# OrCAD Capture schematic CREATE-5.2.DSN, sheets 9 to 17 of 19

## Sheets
9 P18: changes since K4R3.3: title: Change Log
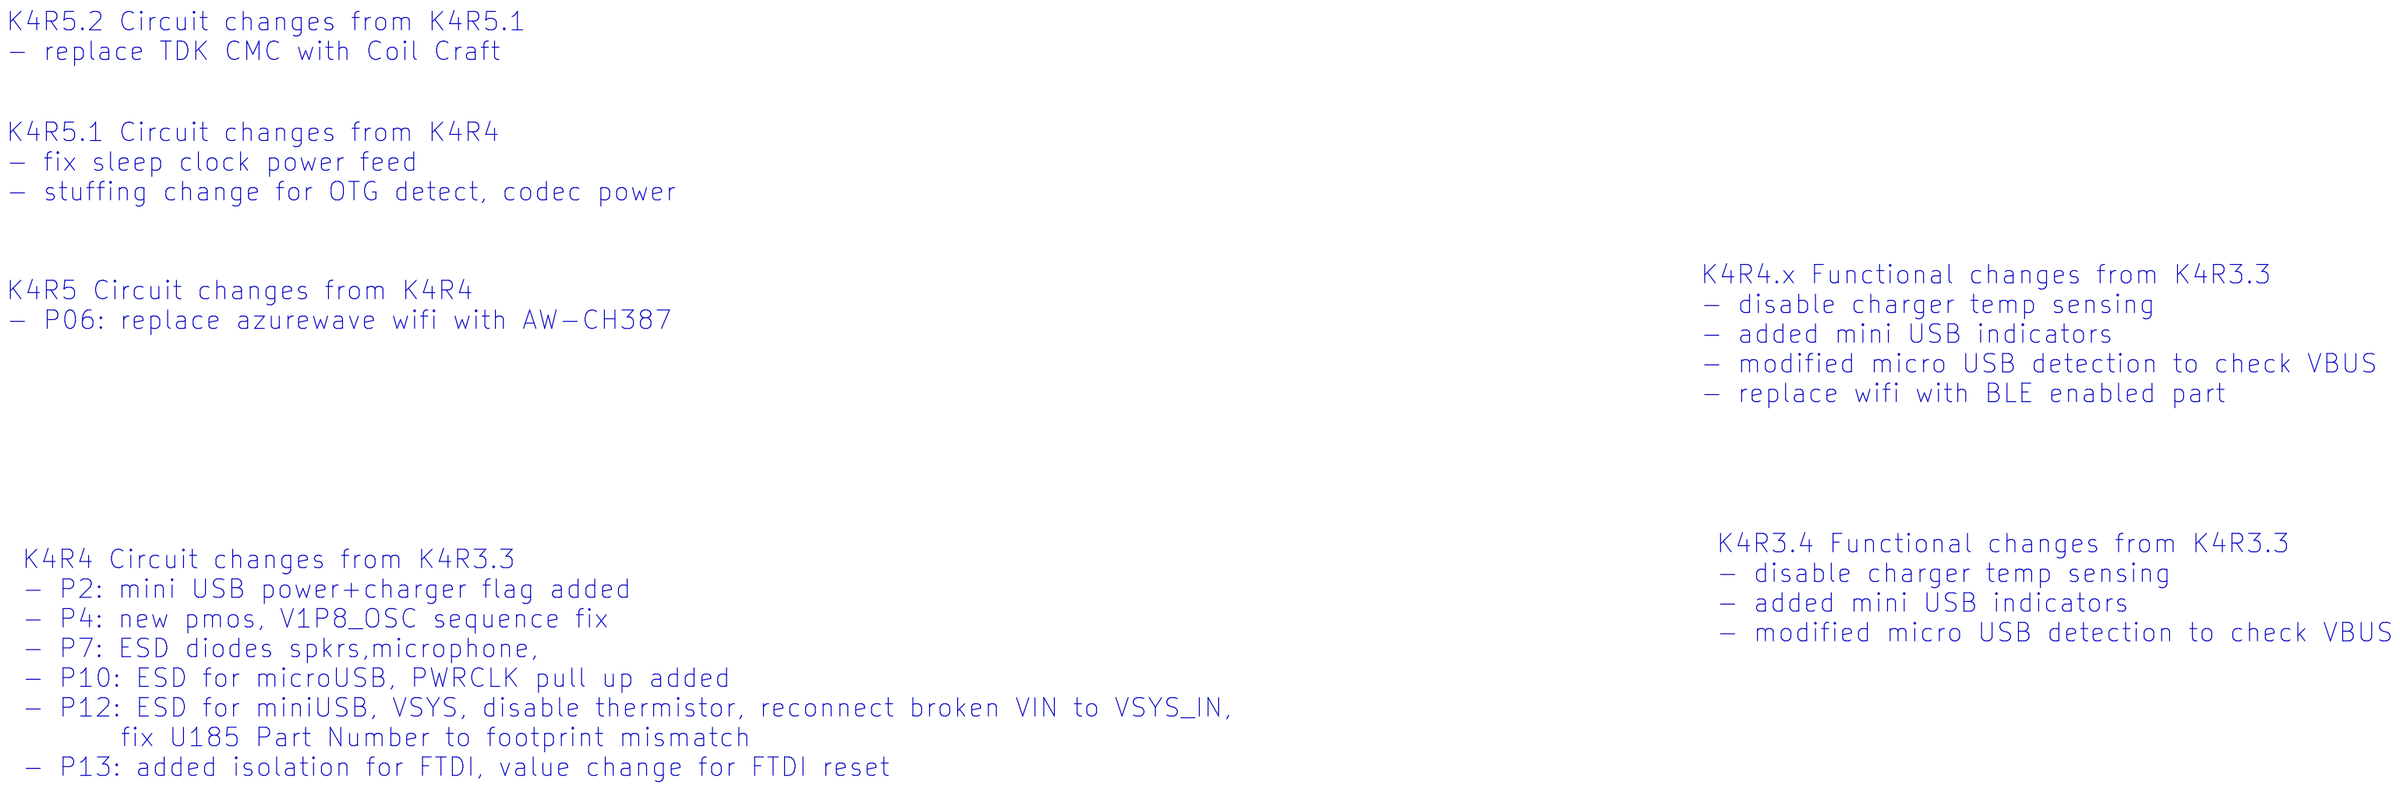
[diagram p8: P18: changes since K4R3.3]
10 P11: System Power Rails: size Custom; title: System Power
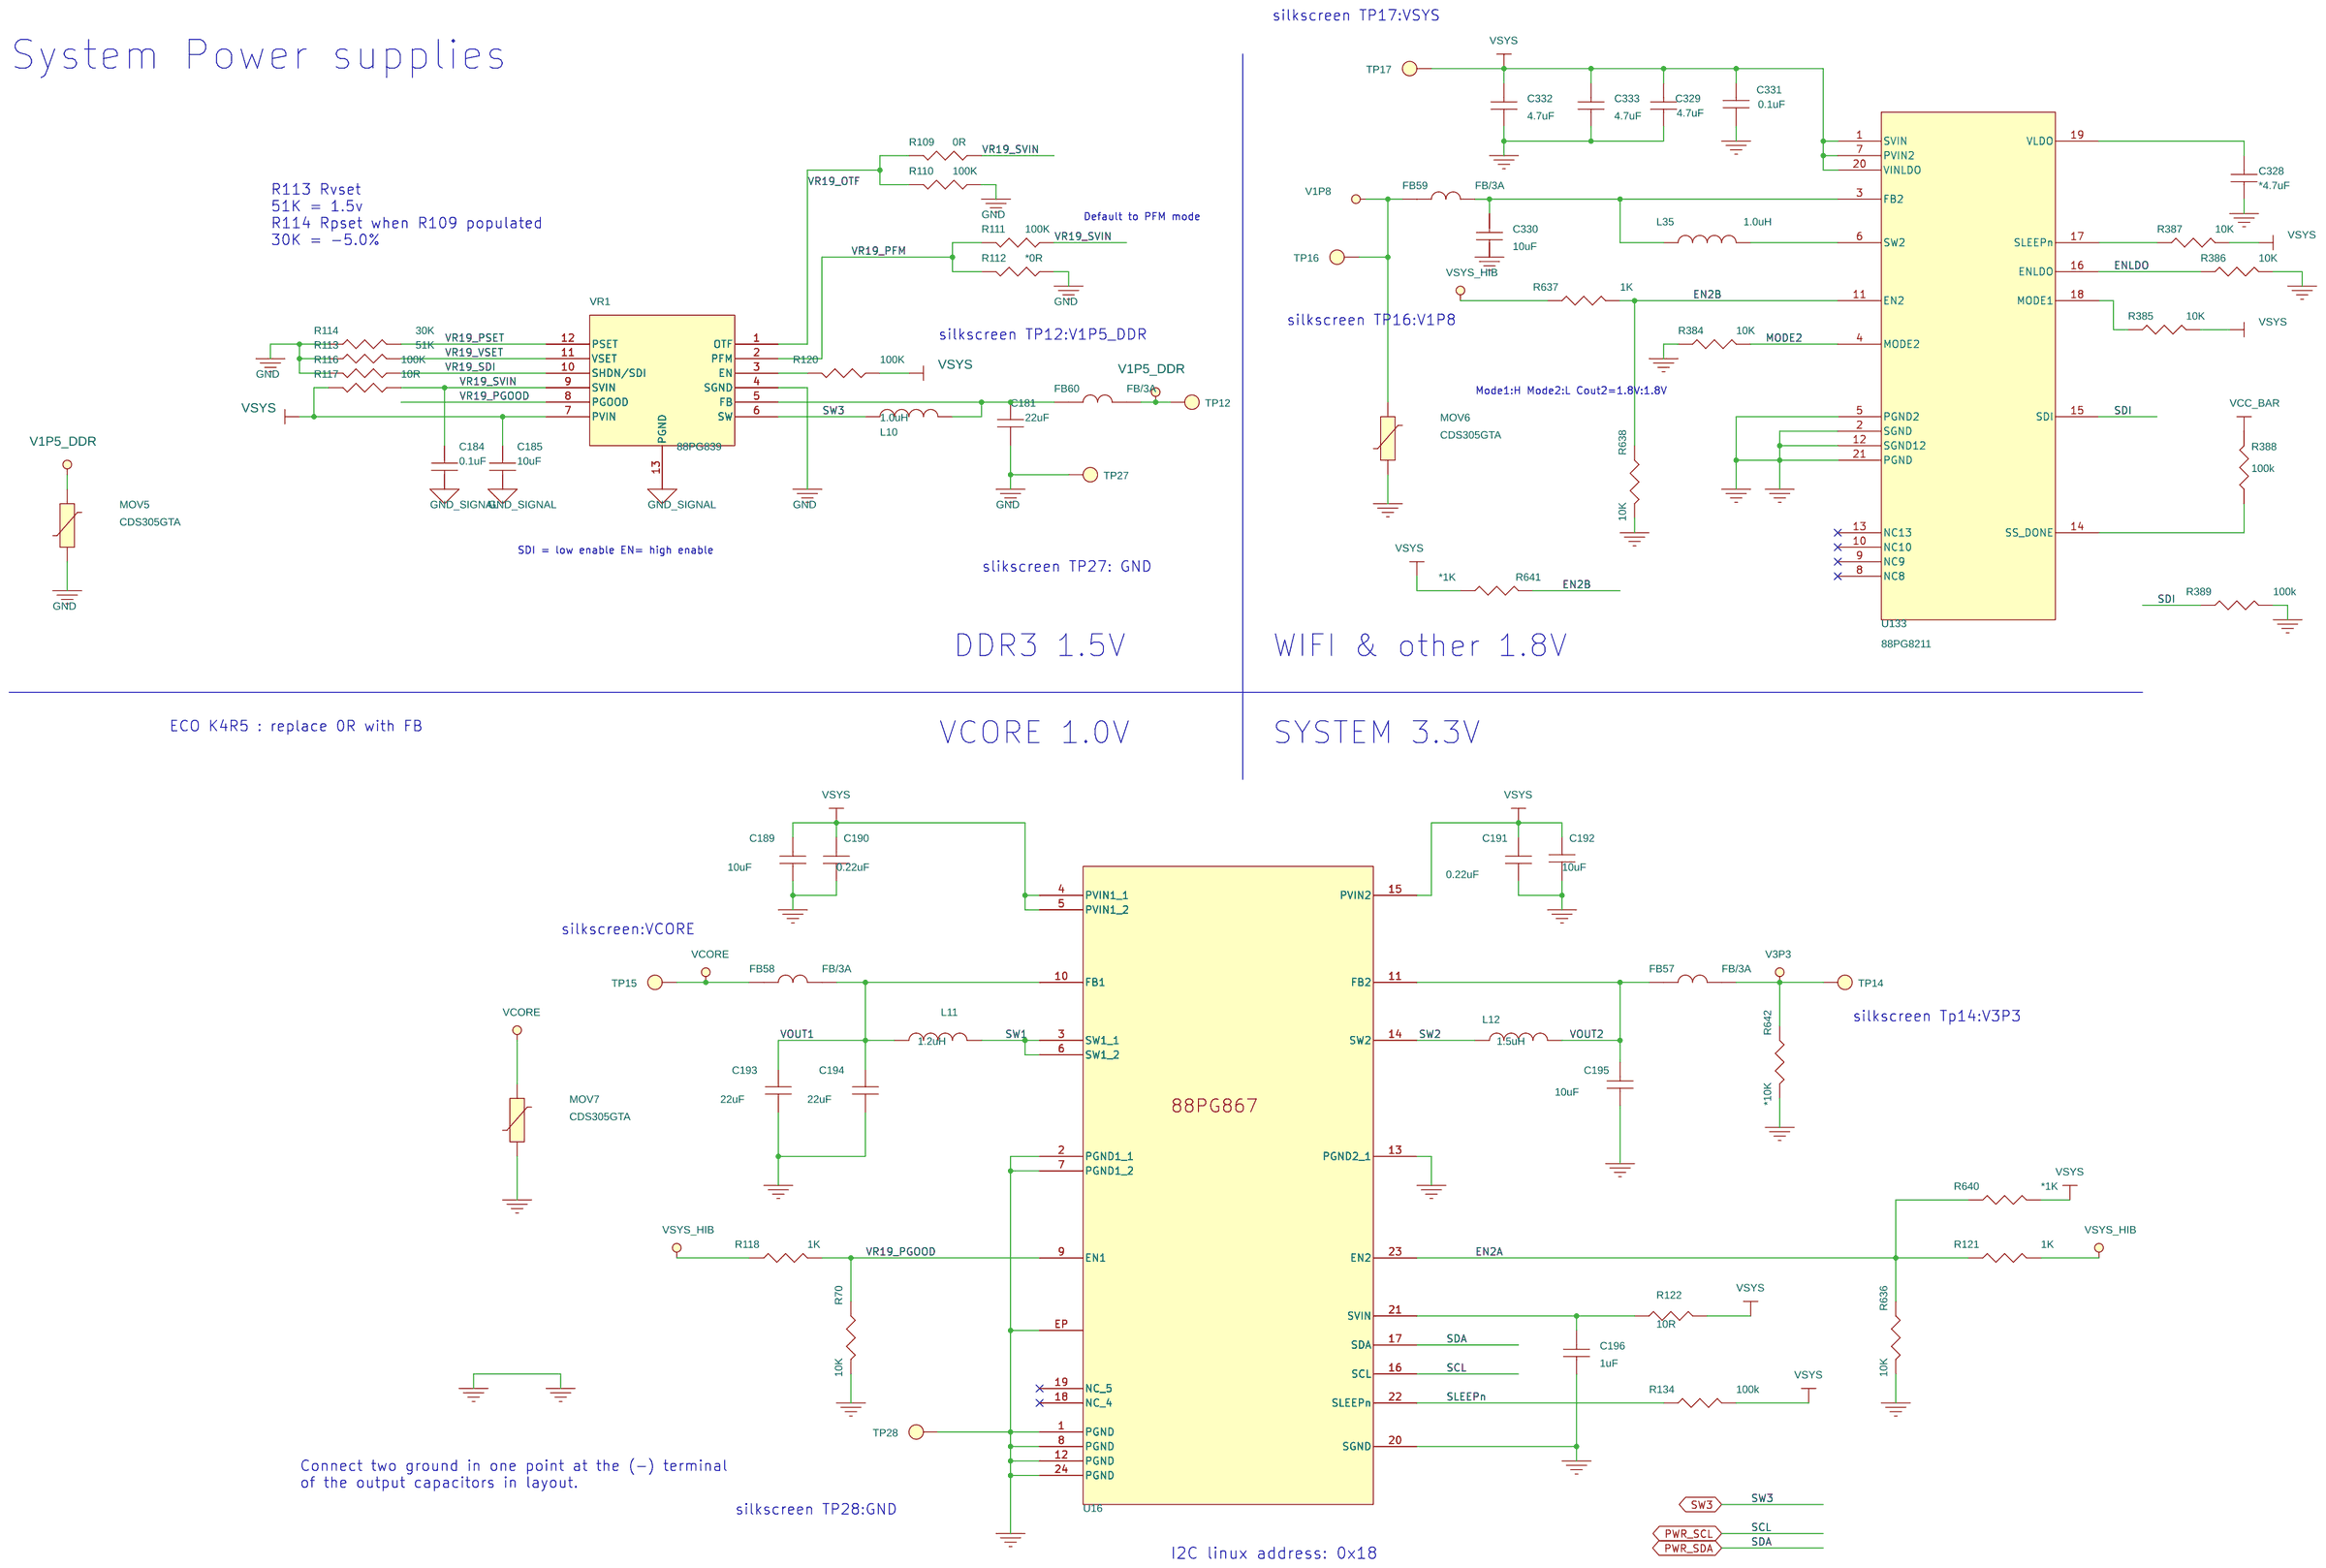
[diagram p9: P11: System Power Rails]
11 P09: Power architecture: title: Power Distribution
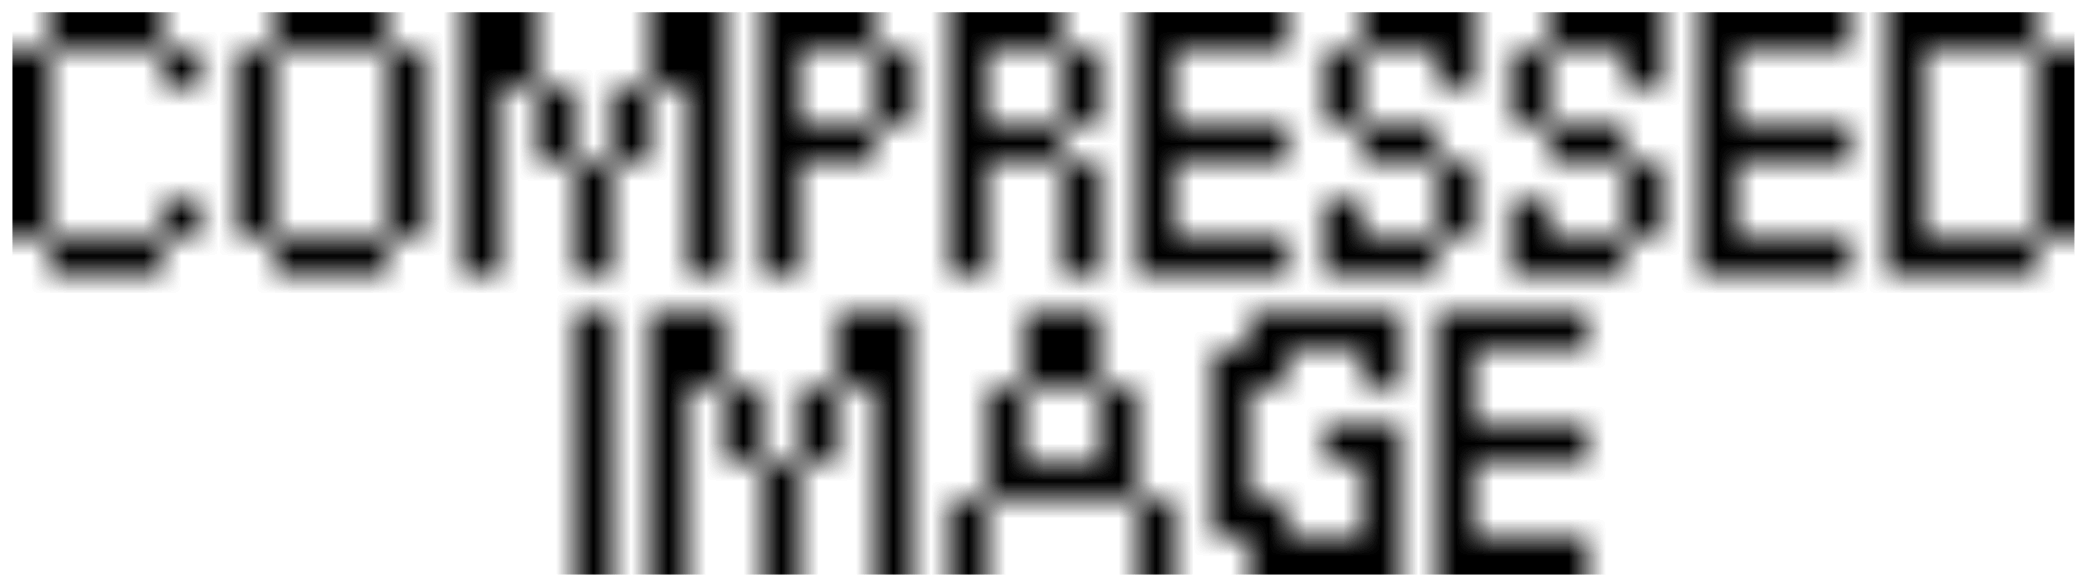
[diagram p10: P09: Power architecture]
12 P01: Create Block Diagram: title: Main Board; rev: 5.1
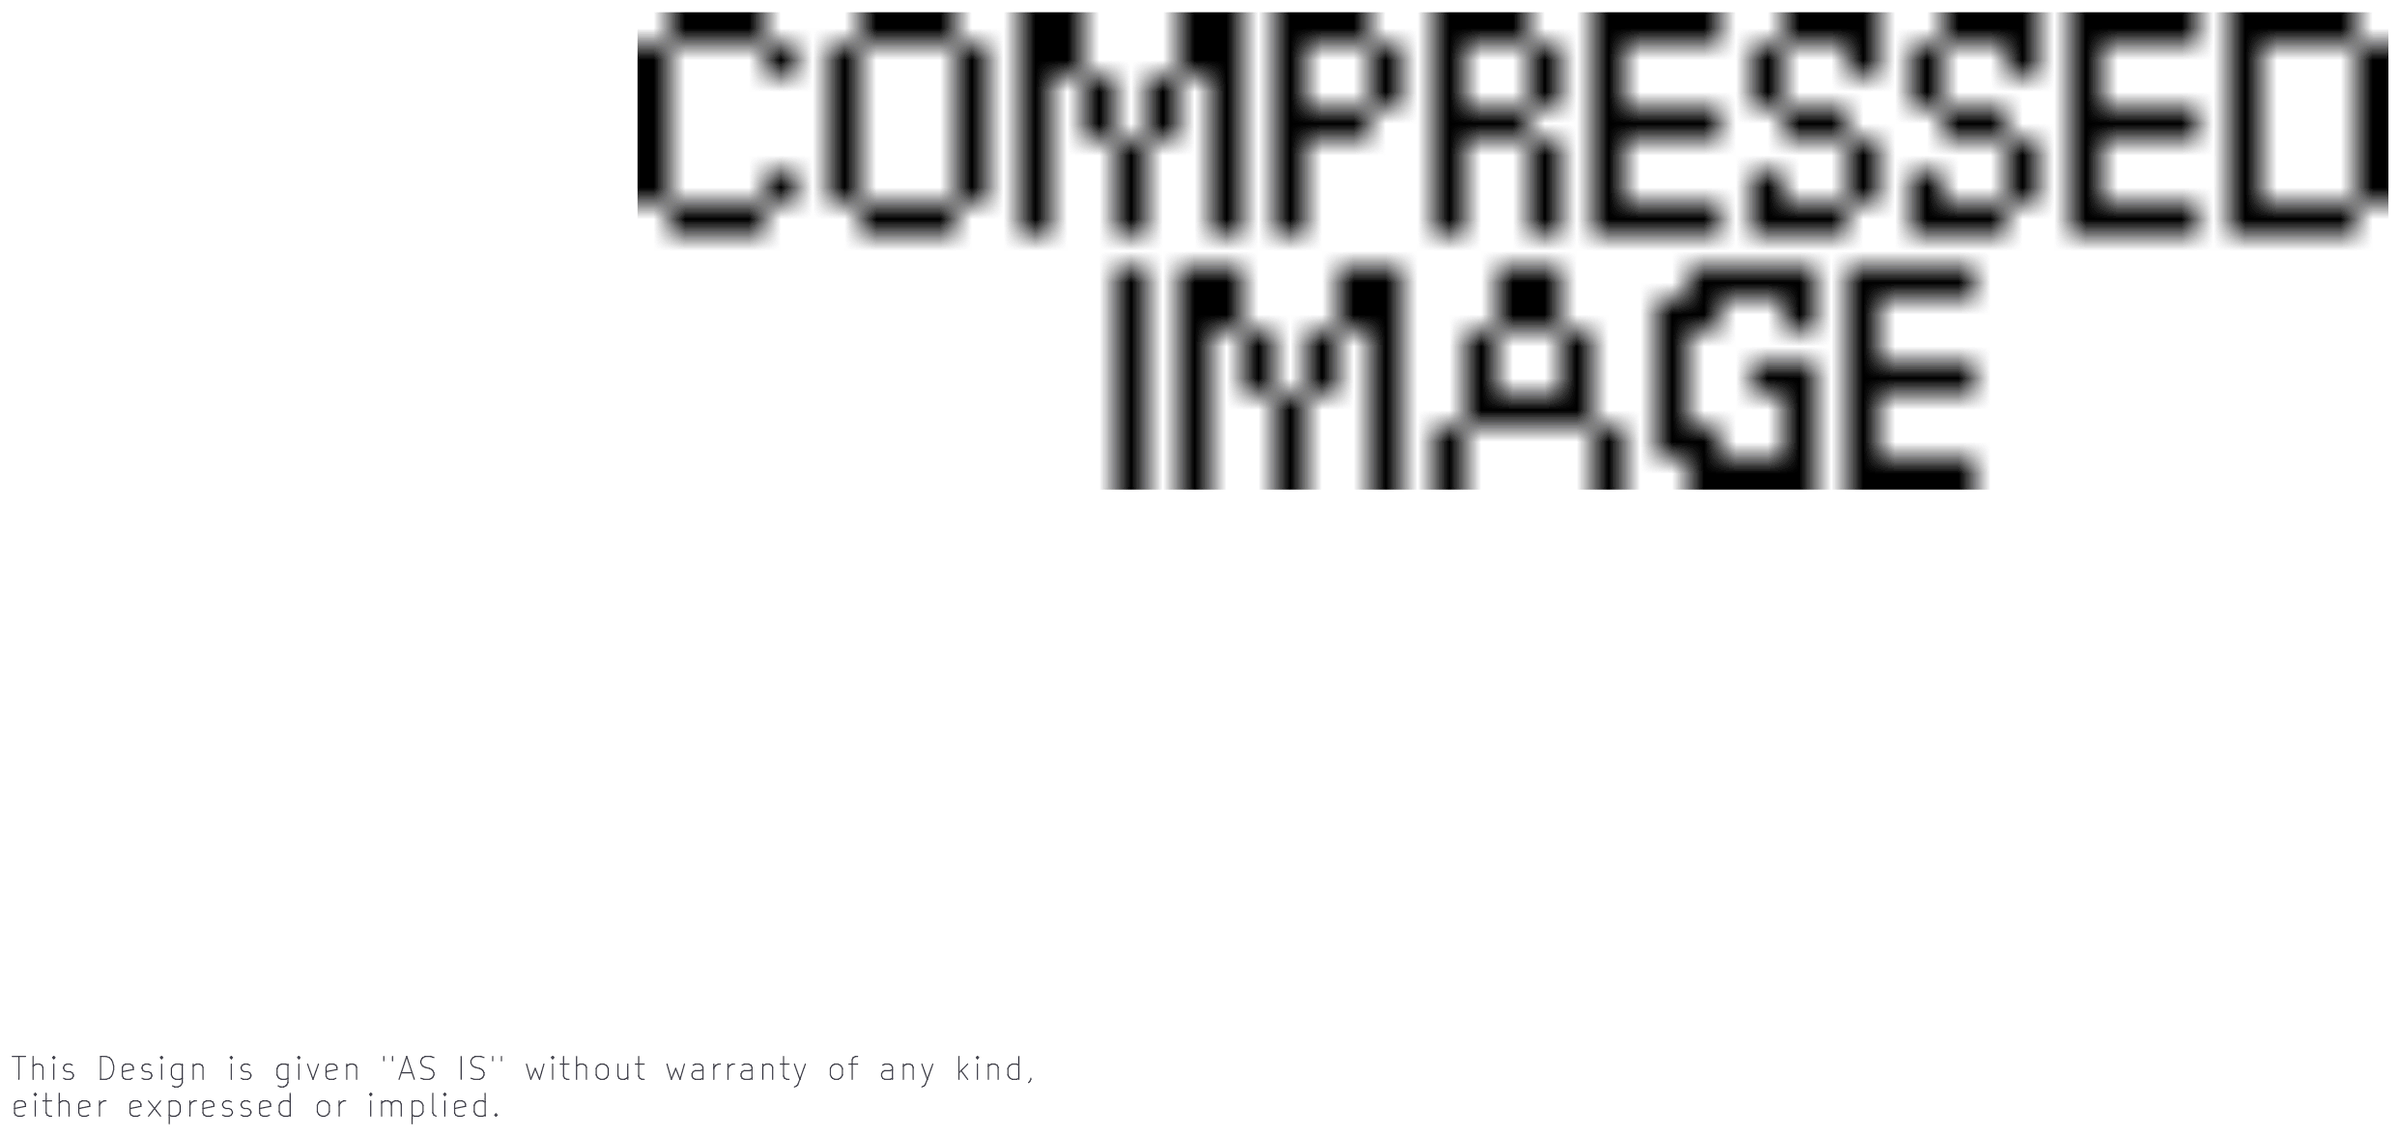
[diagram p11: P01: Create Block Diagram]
13 P10: Power Input and switch: size Custom; title: Power Input & switch
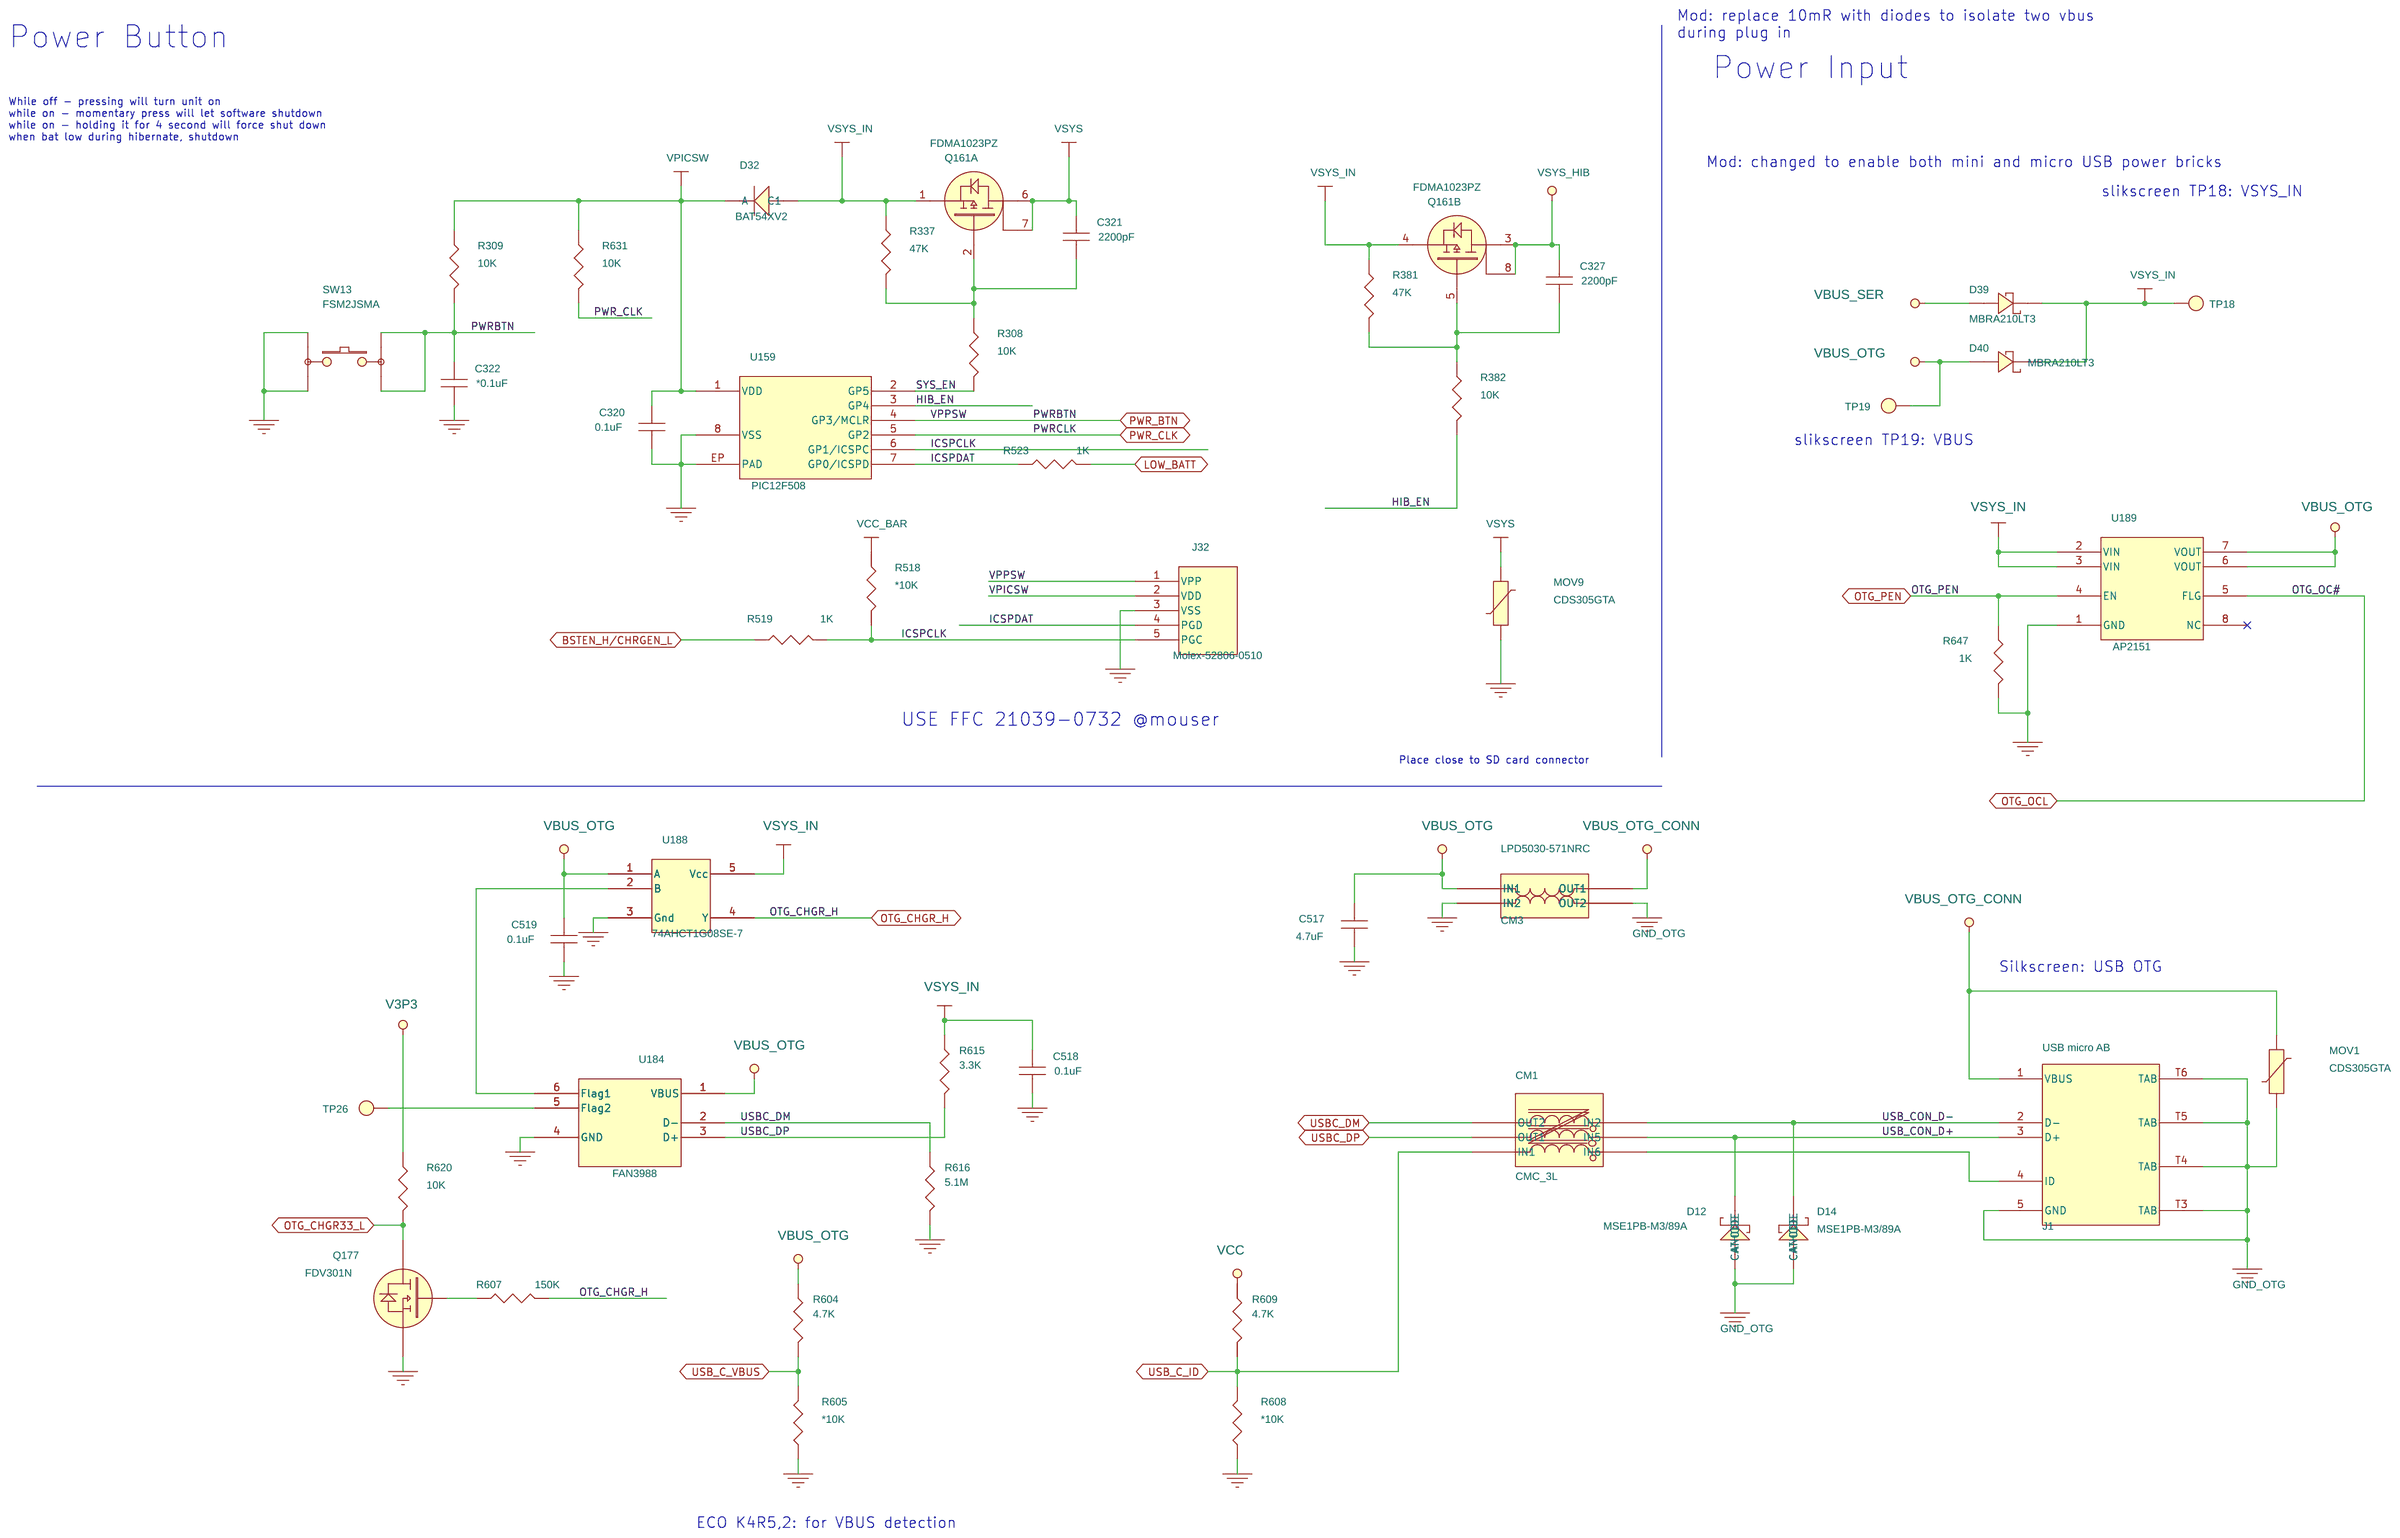
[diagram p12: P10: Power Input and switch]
14 P03: ASPEN-AUDIO/SDIO/MISC: size Custom; title: ASPEN-SPI/SDIO/etc
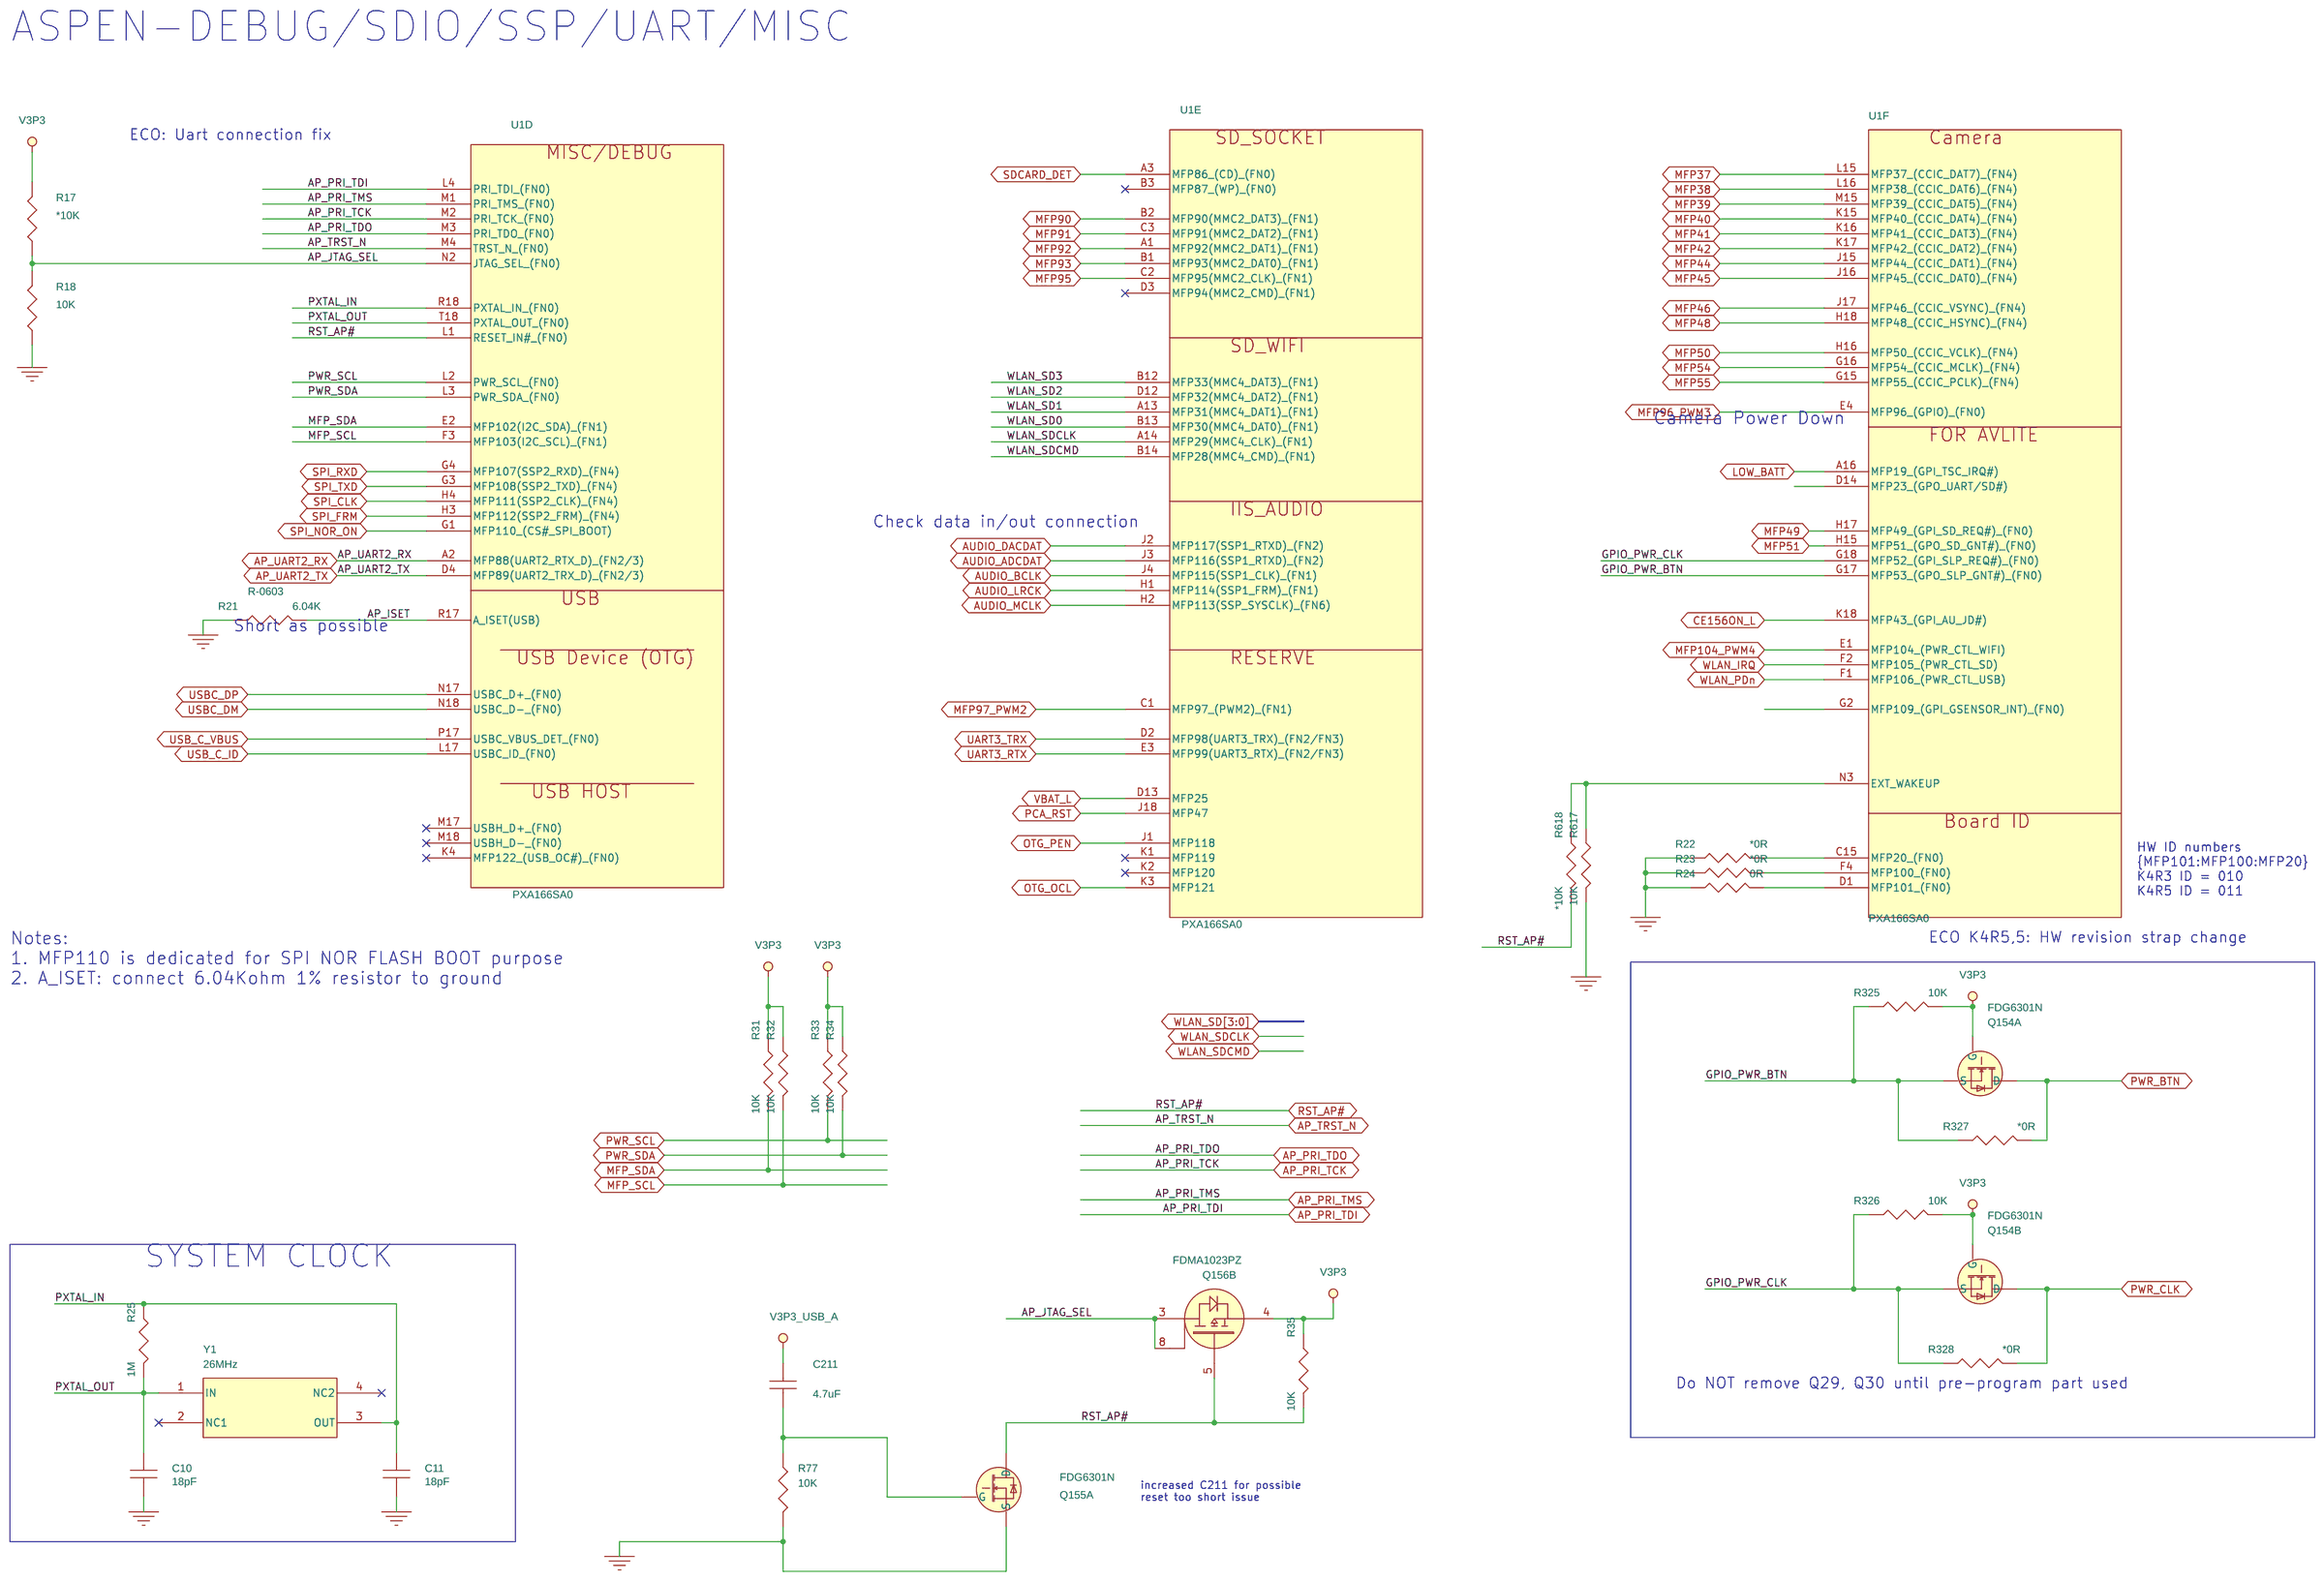
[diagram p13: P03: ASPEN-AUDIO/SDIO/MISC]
15 P19: changes K4R2 to K4R3.3: title: Change Log
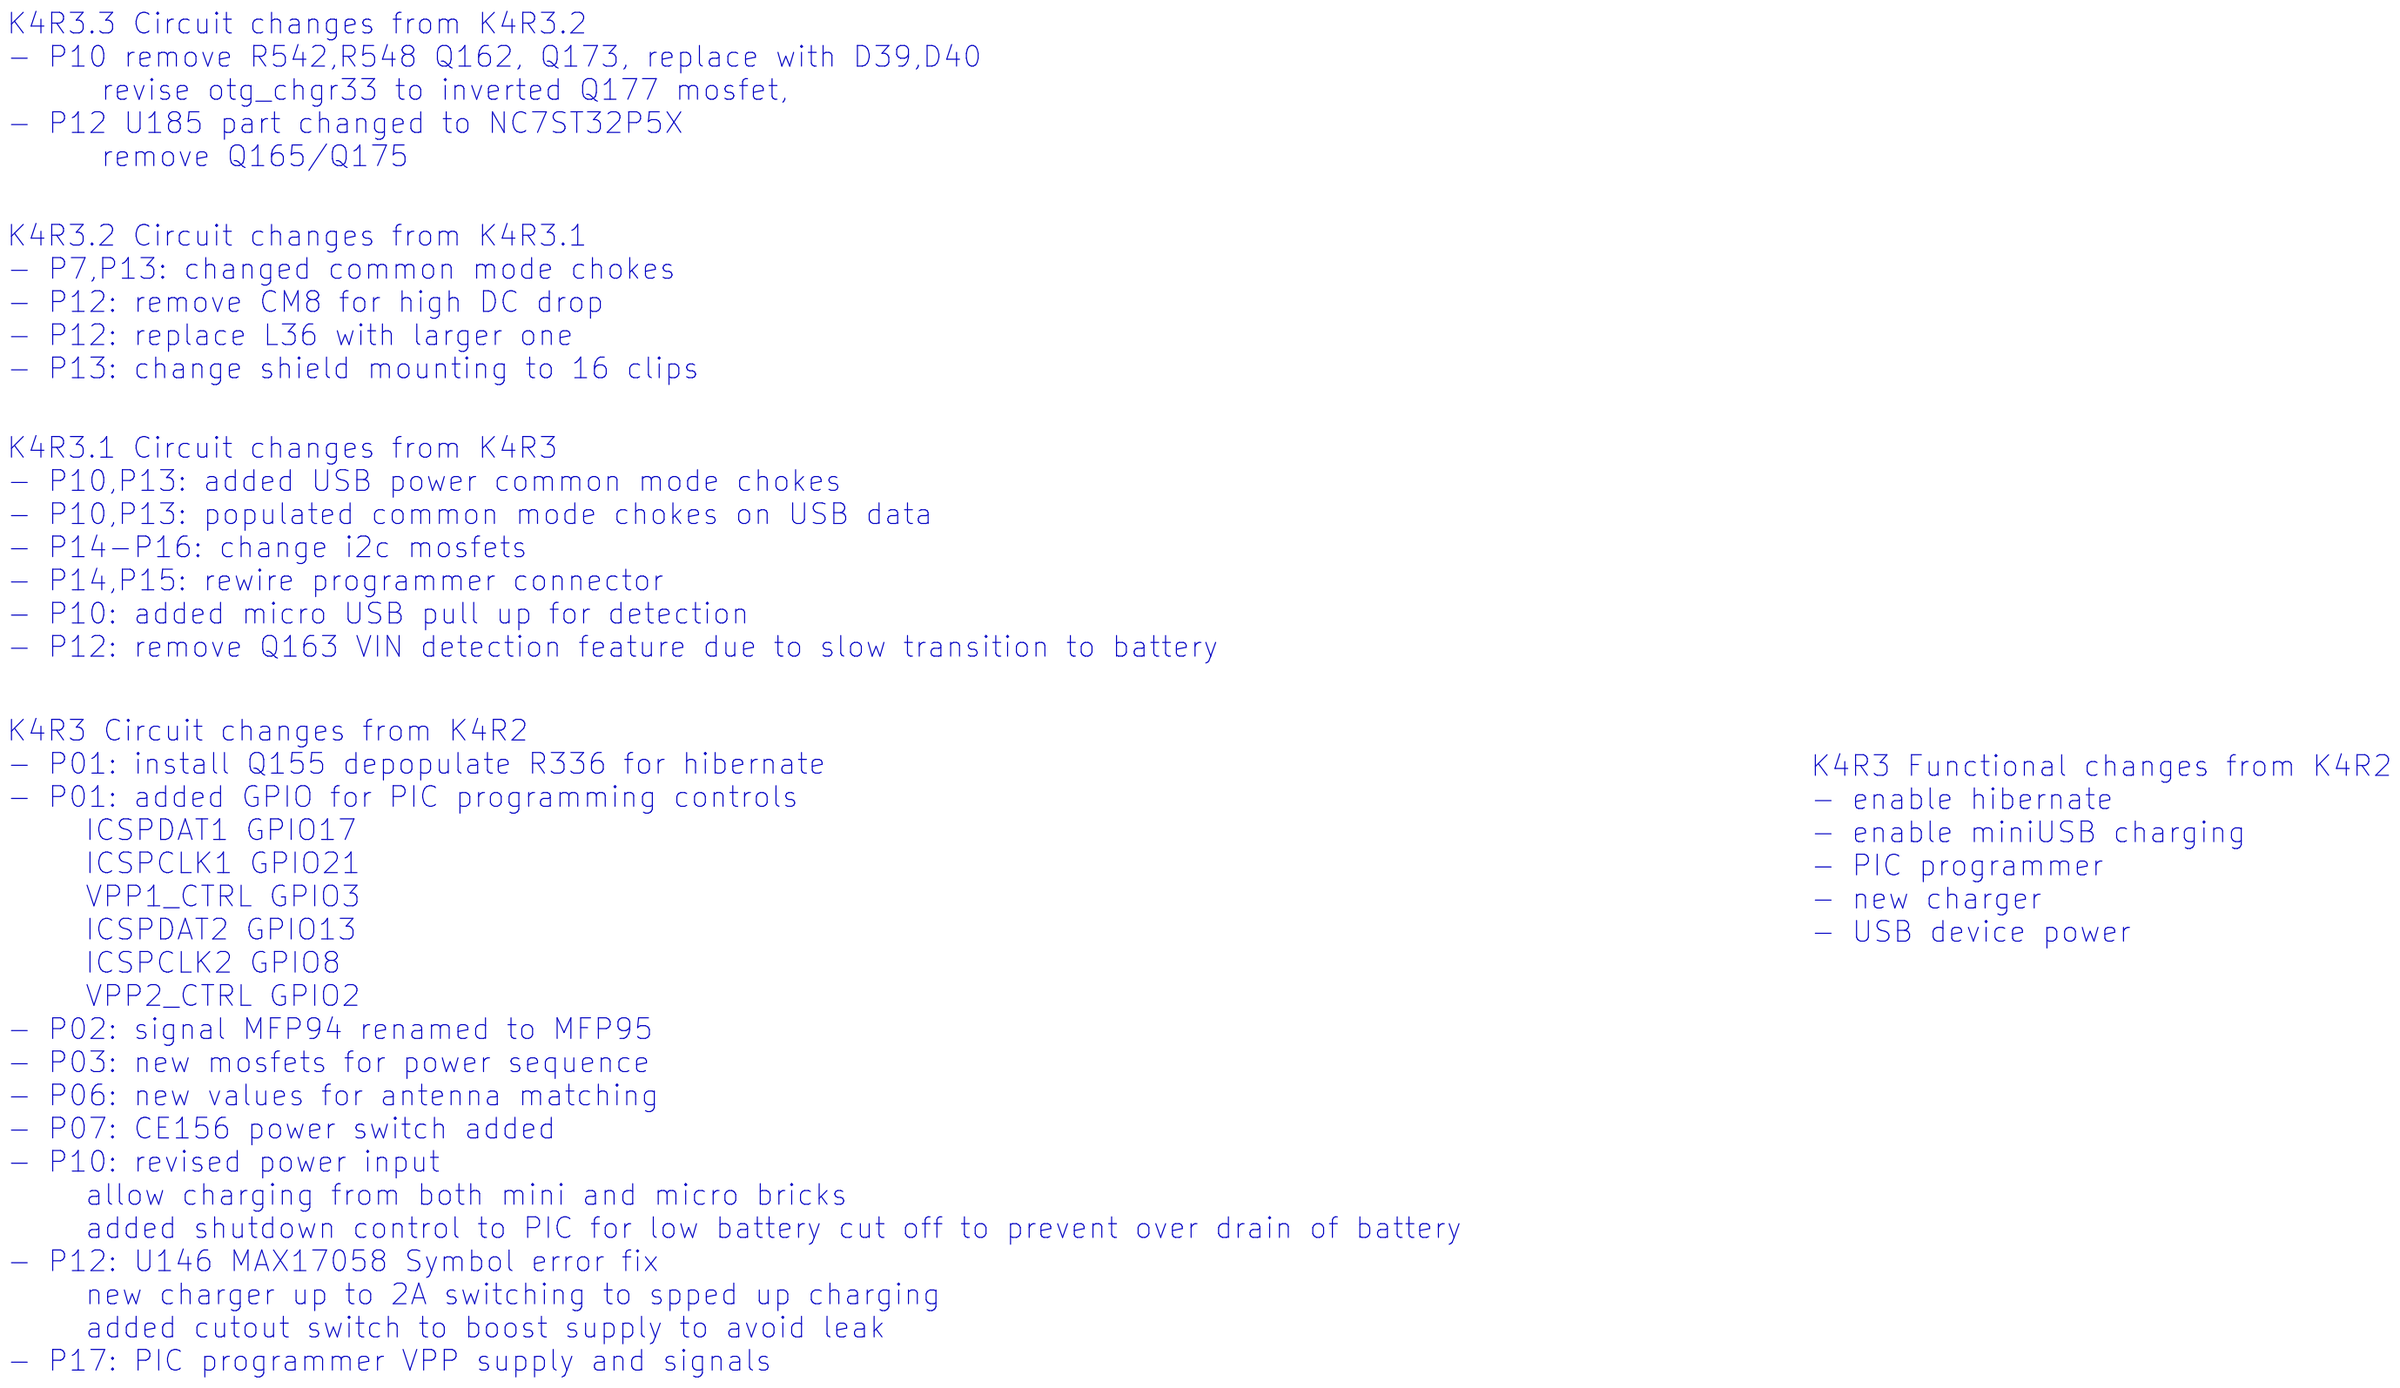
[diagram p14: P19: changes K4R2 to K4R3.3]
16 P12: batt, GG, Bst and chgr: size Custom; title: Power Path
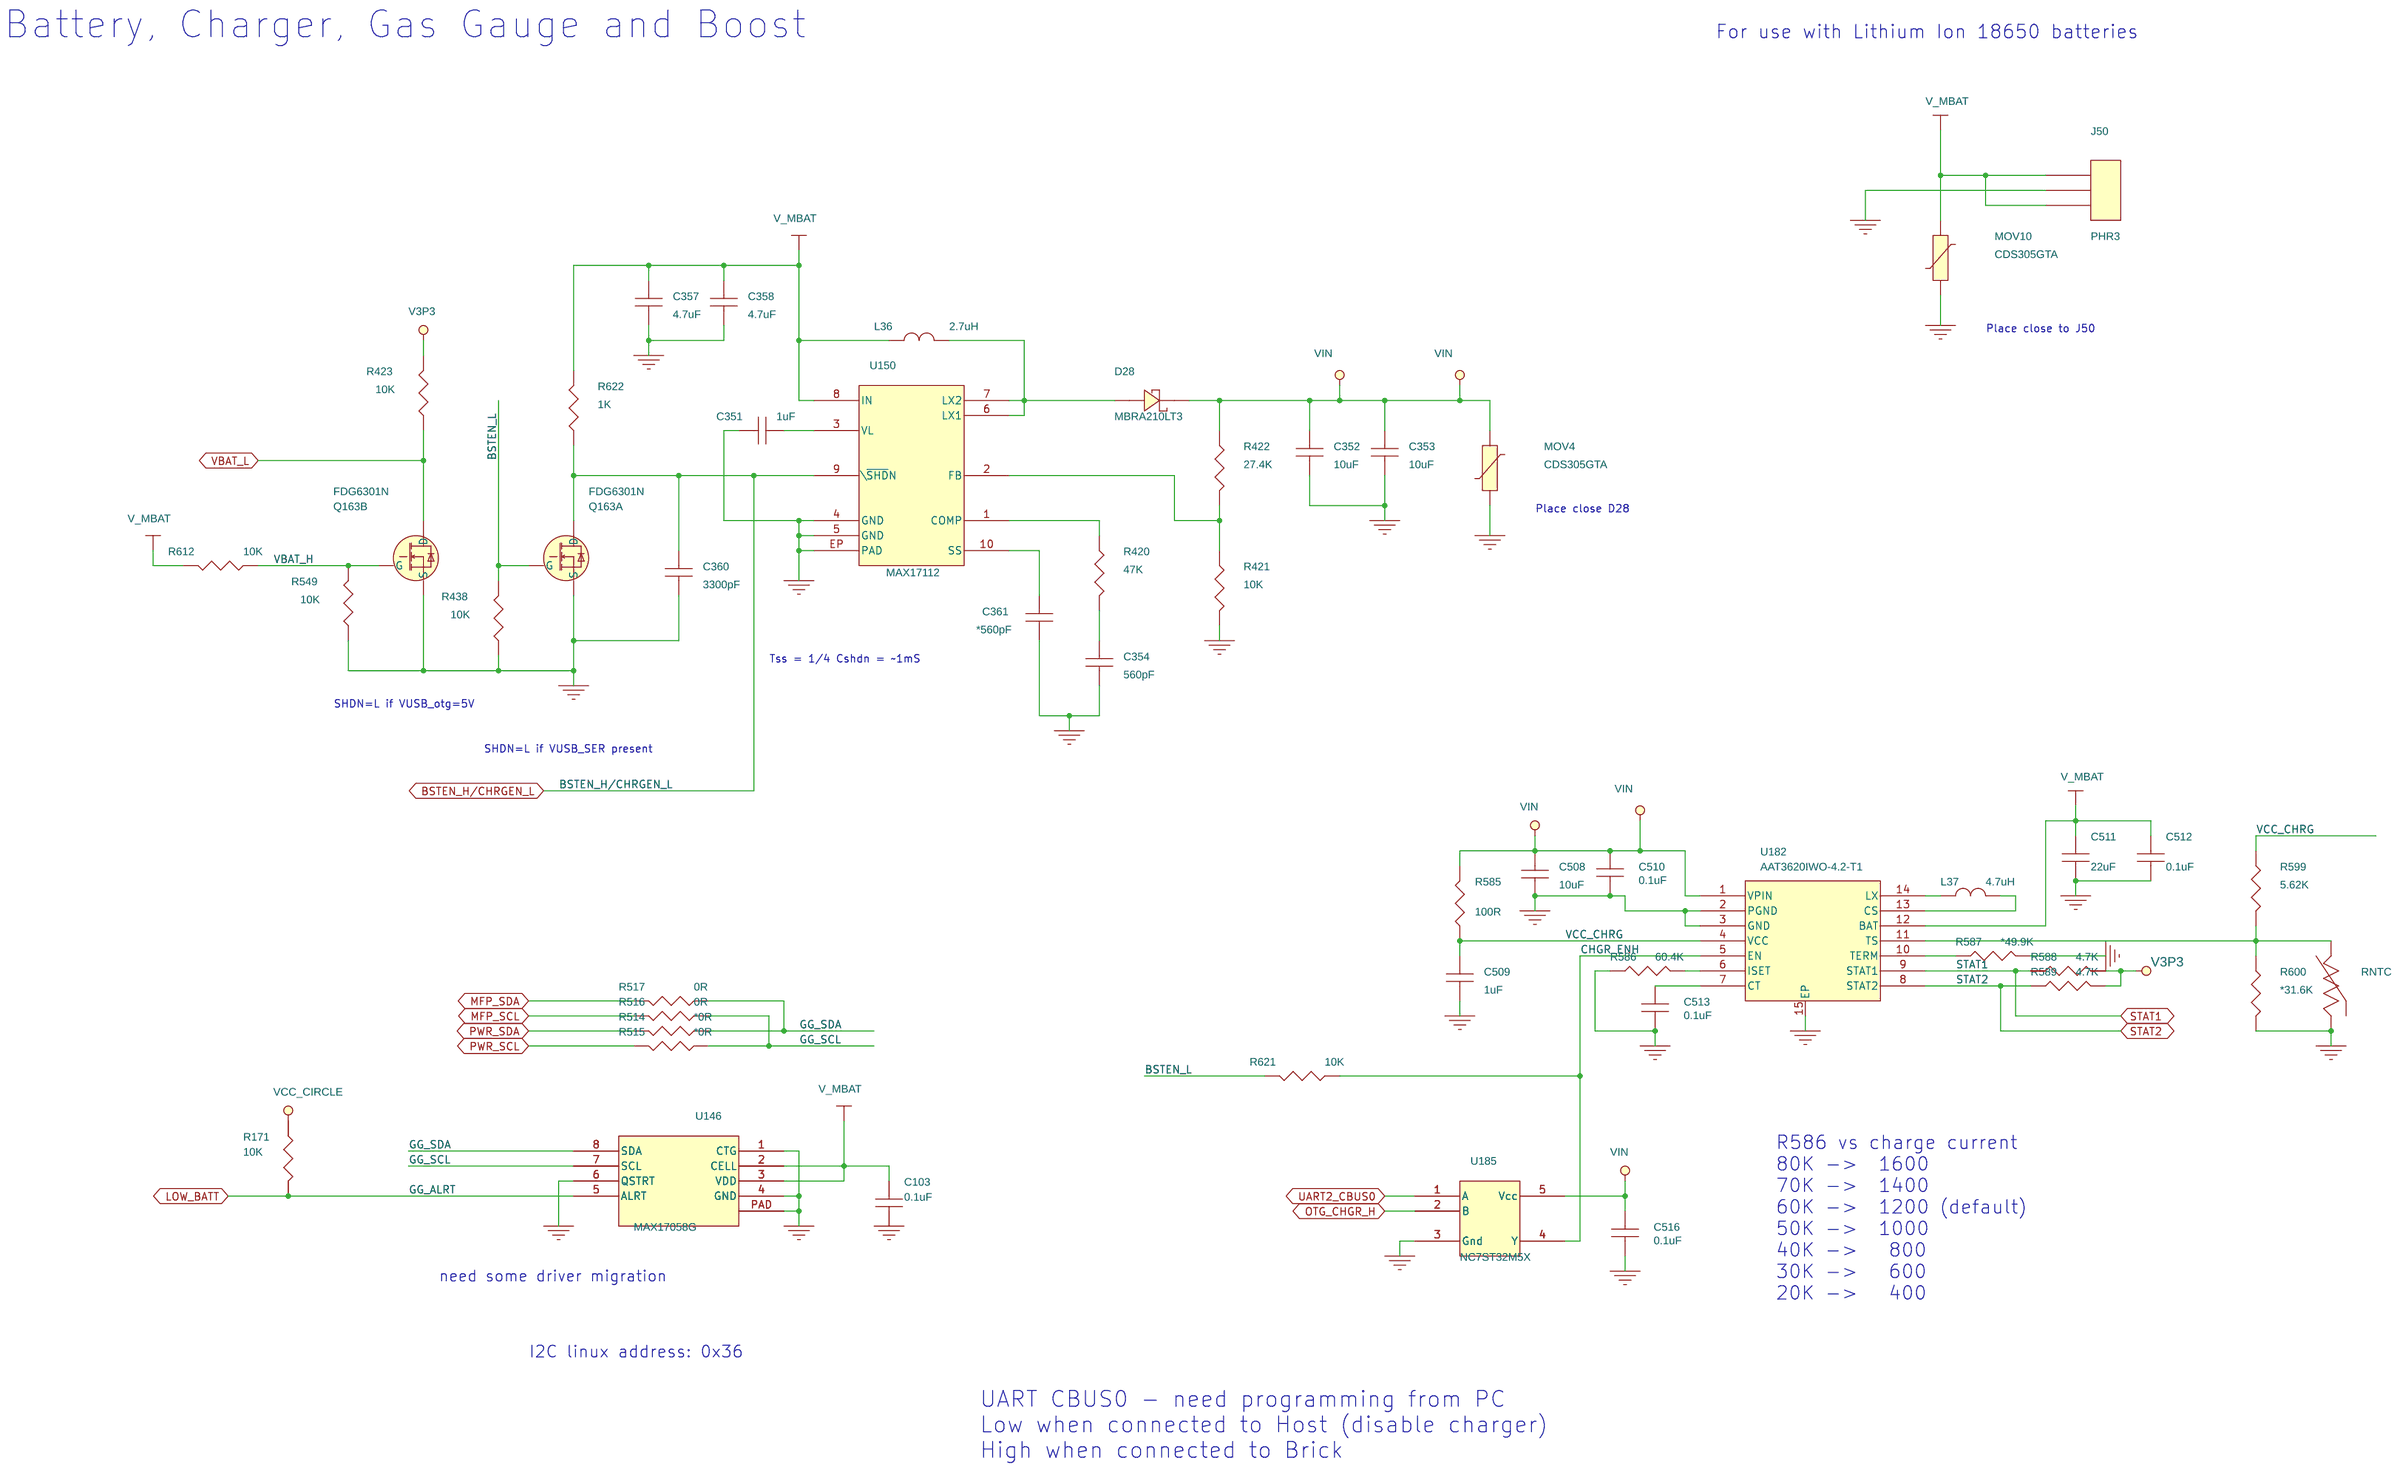
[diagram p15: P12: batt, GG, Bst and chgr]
17 P14: Front access 8 pin conn 1: size Custom; title: Front Conn 1
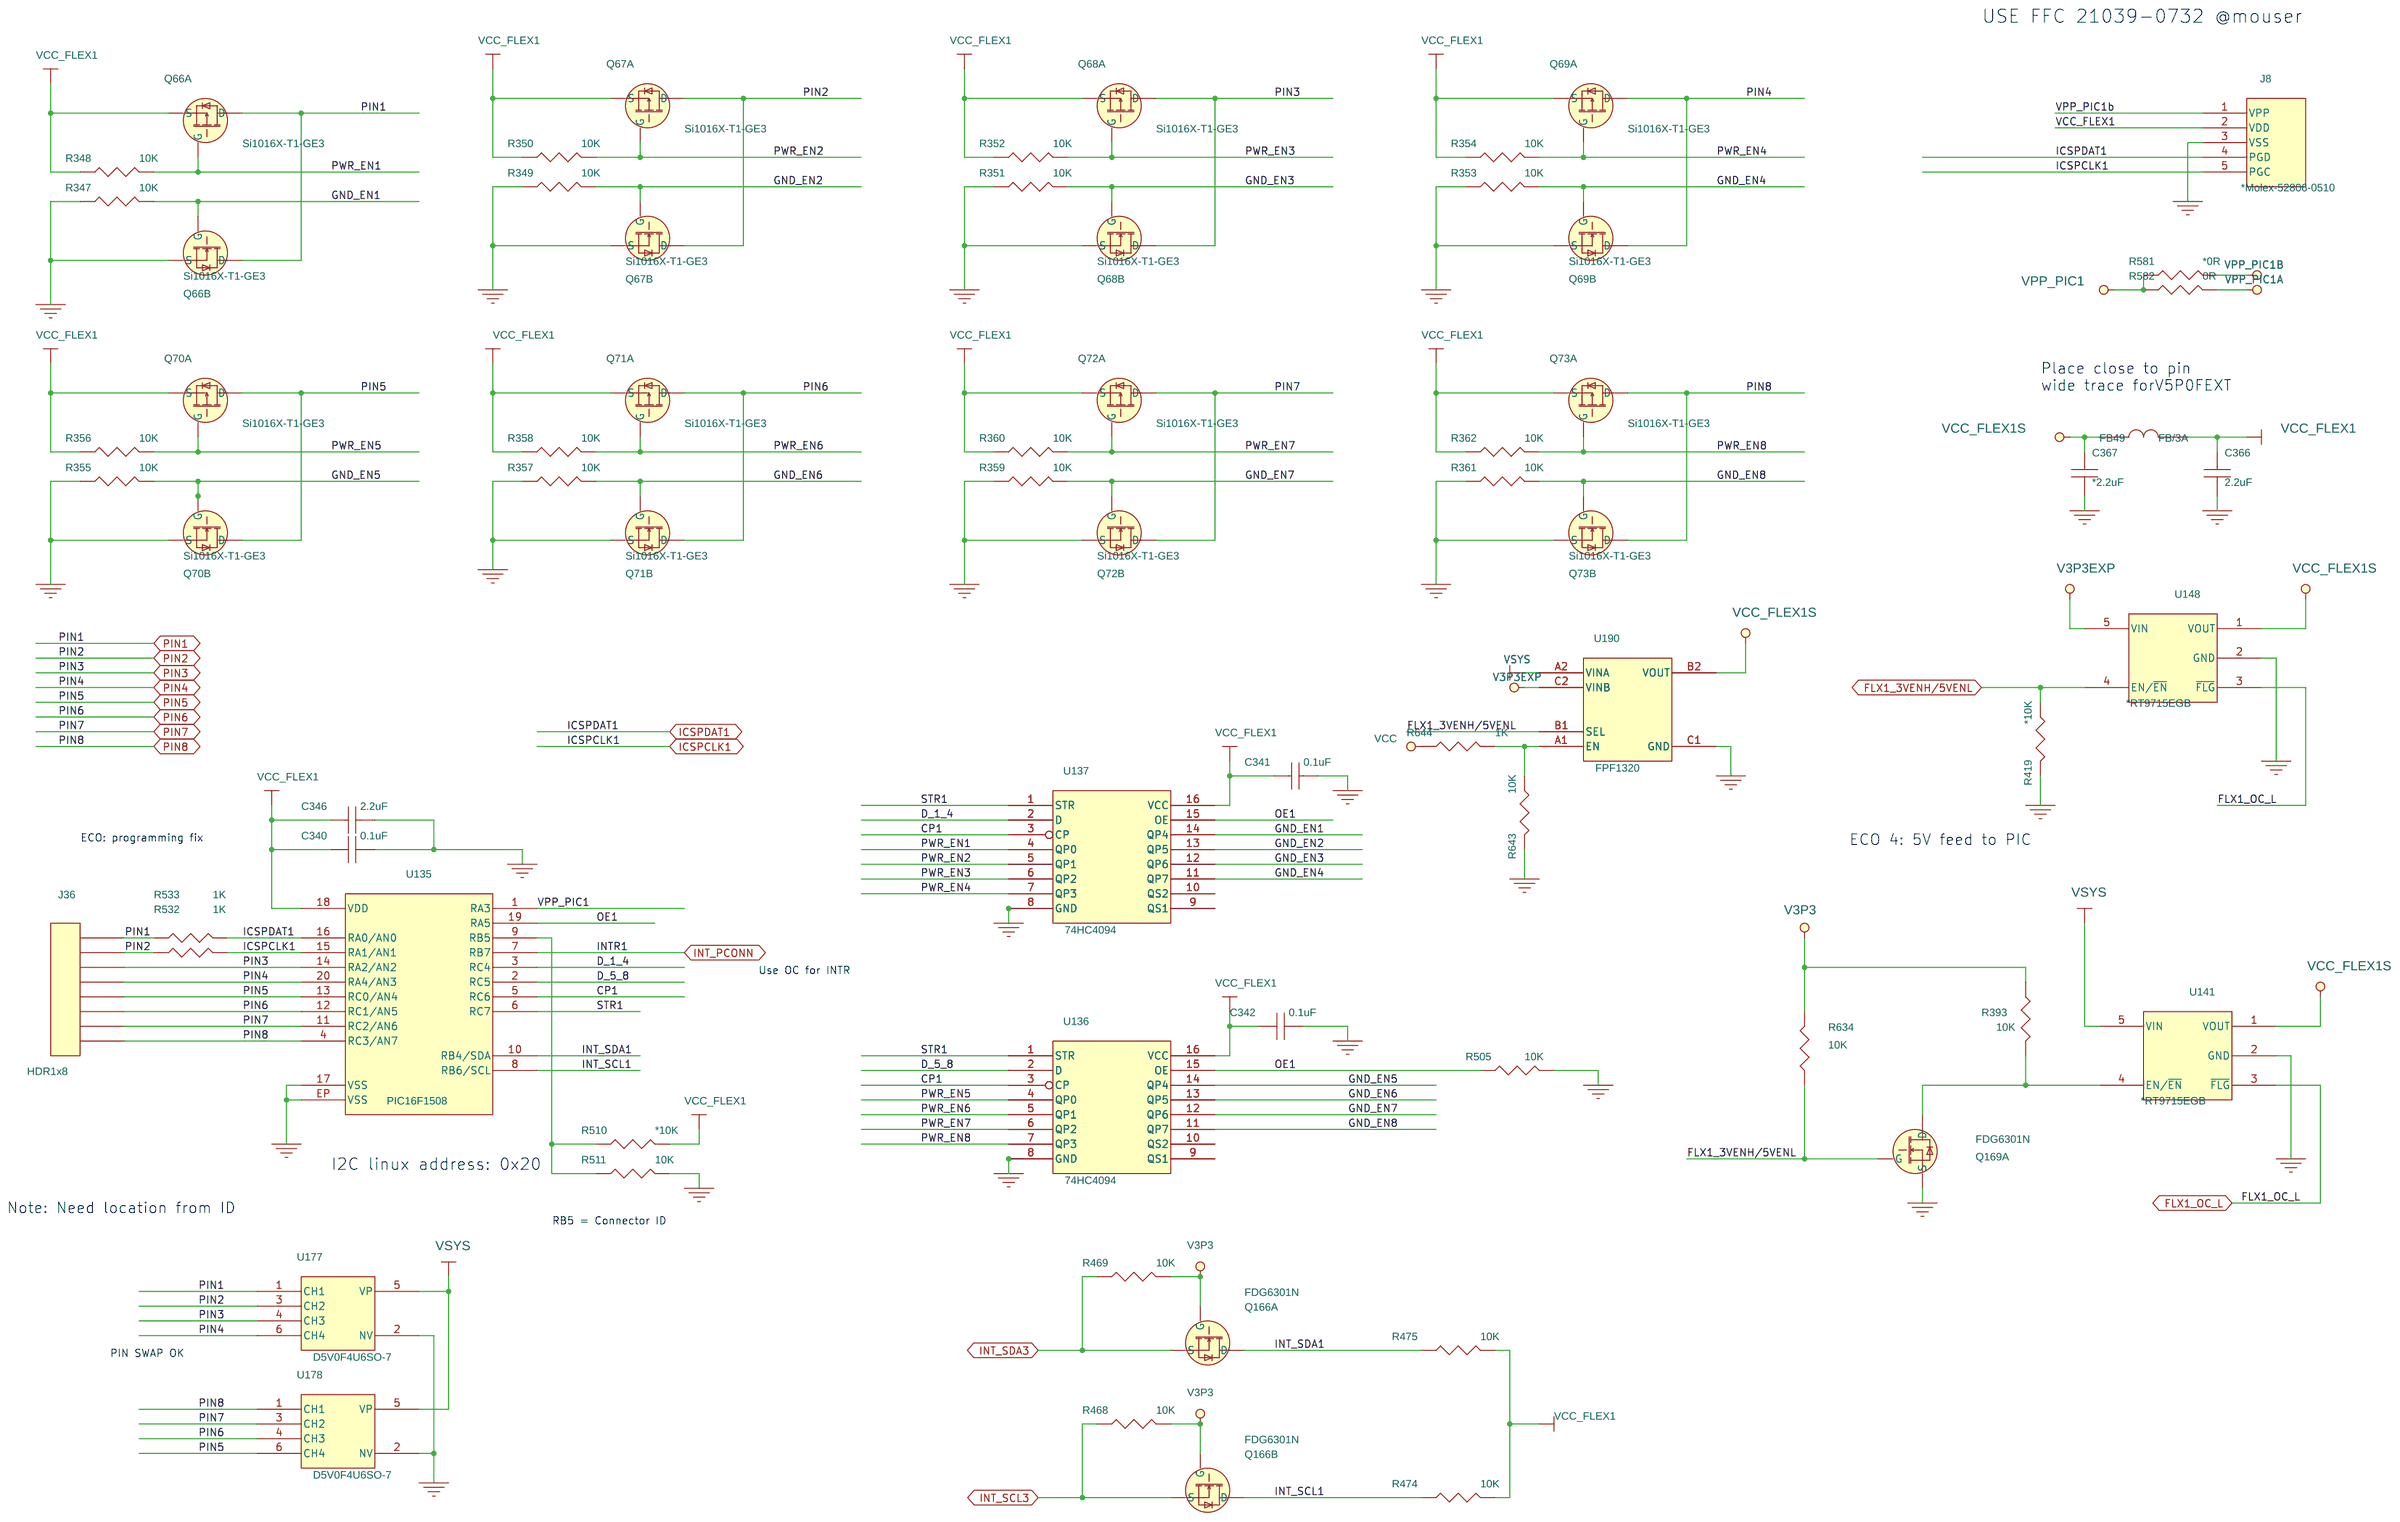
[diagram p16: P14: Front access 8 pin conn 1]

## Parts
sheet P02: ASPEN-MEM/USB/LCD
Q155  FDG6301N  [SC70-6]  (sections A,B)
sheet P03: ASPEN-AUDIO/SDIO/MISC
C10  18pF  [C-0402]
C11  18pF  [C-0402]
C211  4.7uF  [C-0402]
Q154  FDG6301N  [SC70-6]  (sections A,B)
Q156  FDMA1023PZ  [WDFN6]  (sections A,B)
R17  *10K  [R-0402]
R18  10K  [R-0402]
R21  6.04K  [R-0603]
R22  *0R  [R-0402]
R23  *0R  [R-0402]
R24  0R  [R-0402]
R25  1M  [R-0402]
R31  10K  [R-0402]
R32  10K  [R-0402]
R33  10K  [R-0402]
R34  10K  [R-0402]
R35  10K  [R-0402]
R77  10K  [R-0402]
R325  10K  [R-0402]
R326  10K  [R-0402]
R327  *0R  [R-0402]
R328  *0R  [R-0402]
R617  10K  [R-0402]
R618  *10K  [R-0402]
U1  PXA166SA0  [fbga-18x18-320]  (sections A,B,C,D,E,F)
Y1  26MHz  [o-3_2X2_5-4g]
sheet P10: Power Input and switch
C320  0.1uF  [C-0402]
C321  2200pF  [C-0402]
C322  *0.1uF  [C-0402]
C327  2200pF  [C-0402]
C517  4.7uF  [C-0603]
C518  0.1uF  [C-0402]
C519  0.1uF  [C-0402]
CM1  CMC_3L  [TDK2520-3L]
CM3  LPD5030-571NRC  [LPD5030]
D12  MSE1PB-M3/89A  [MicroSMP]
D14  MSE1PB-M3/89A  [MicroSMP]
D32  BAT54XV2  [SOD-523F]
D39  MBRA210LT3  [SMA]
D40  MBRA210LT3  [SMA]
J1  USB micro AB  [USB-MICRO-AB-HIROSE]
J32  Molex-52806-0510  [Molex_52806_0510]
MOV1  CDS305GTA  [D0603]
MOV9  CDS305GTA  [D0603]
Q161  FDMA1023PZ  [WDFN6]  (sections A,B)
Q177  FDV301N  [SOT-23a]
R308  10K  [R-0402]
R309  10K  [R-0402]
R337  47K  [R-0402]
R381  47K  [R-0402]
R382  10K  [R-0402]
R518  *10K  [R-0402]
R519  1K  [R-0402]
R523  1K  [R-0402]
R604  4.7K  [R-0402]
R605  *10K  [R-0402]
R607  150K  [R-0402]
R608  *10K  [R-0402]
R609  4.7K  [R-0402]
R615  3.3K  [R-0402]
R616  5.1M  [R-0402]
R620  10K  [R-0402]
R631  10K  [R-0402]
R647  1K  [R-0402]
SW13  FSM2JSMA  [FSM2JSMATR]
TP18  *T_POINT  [TP040]
TP19  *T_POINT  [TP040]
TP26  *T_POINT  [TP040]
U159  PIC12F508  [DFN8EP]
U184  FAN3988  [UDFN6]
U188  74AHCT1G08SE-7  [SOT353]
U189  AP2151  [MSOP8]
sheet P11: System Power Rails
C181  22uF  [C-0603]
C184  0.1uF  [C-0402]
C185  10uF  [C-0603]
C189  10uF  [C-0603]
C190  0.22uF  [CAP_0201]
C191  0.22uF  [CAP_0201]
C192  10uF  [C-0603]
C193  22uF  [C-0603]
C194  22uF  [C-0603]
C195  10uF  [C-0402]
C196  1uF  [C0402]
C328  *4.7uF  [CAP_0603]
C329  4.7uF  [C-0603]
C330  10uF  [C-0402]
C331  0.1uF  [C-0402]
C332  4.7uF  [C-0603]
C333  4.7uF  [C-0603]
FB57  FB/3A  [L-0603]
FB58  FB/3A  [L-0603]
FB59  FB/3A  [L-0603]
FB60  FB/3A  [L-0603]
L10  1.0uH  [FLF3215]
L11  1.2uH  [VLC5020T]
L12  1.5uH  [INDUCTOR_MDT2520_CN_SERIES]
L35  1.0uH  [INDUCTOR_MDT2520_CR_SERIES]
MOV5  CDS305GTA  [D0603]
MOV6  CDS305GTA  [D0603]
MOV7  CDS305GTA  [D0603]
R70  10K  [R-0402]
R109  0R  [R-0402]
R110  100K  [R-0402]
R111  100K  [R-0402]
R112  *0R  [R-0402]
R113  51K  [R-0402]
R114  30K  [R-0402]
R116  100K  [R-0402]
R117  10R  [R-0402]
R118  1K  [R-0402]
R120  100K  [R-0402]
R121  1K  [R-0402]
R122  10R  [R-0402]
R134  100k  [R-0402]
R384  10K  [R-0402]
R385  10K  [R-0402]
R386  10K  [R-0402]
R387  10K  [R-0402]
R388  100k  [R-0402]
R389  100k  [R-0402]
R636  10K  [R-0402]
R637  1K  [R-0402]
R638  10K  [R-0402]
R640  *1K  [R-0402]
R641  *1K  [R-0402]
R642  *10K  [R-0402]
TP12  *T_POINT  [TP040]
TP14  *T_POINT  [TP040]
TP15  *T_POINT  [TP040]
TP16  *T_POINT  [TP040]
TP17  *T_POINT  [TP040]
TP27  *T_POINT  [TP040]
TP28  *T_POINT  [TP040]
U16  88PG867  [3x4QFN24]
U133  88PG8211  [4X3QFN16_PAD_LENGTH_0P8MM_32MIL]
VR1  88PG839  [DFN-12]
sheet P12: batt, GG, Bst and chgr
C103  0.1uF  [C-0402]
C351  1uF  [C0402]
C352  10uF  [C-0603]
C353  10uF  [C-0603]
C354  560pF  [C-0402]
C357  4.7uF  [C-0603]
C358  4.7uF  [C-0603]
C360  3300pF  [C-0402]
C361  *560pF  [C-0402]
C508  10uF  [C-0603]
C509  1uF  [C0402]
C510  0.1uF  [C-0402]
C511  22uF  [C-1210]
C512  0.1uF  [C-0402]
C513  0.1uF  [C-0402]
C516  0.1uF  [C-0402]
D28  MBRA210LT3  [SMA]
J50  PHR3  [JST_PHR3P_2mm]
L36  2.7uH  [SDR0403]
L37  4.7uH  [NRS5014]
MOV4  CDS305GTA  [D0603]
MOV10  CDS305GTA  [D0603]
Q163  FDG6301N  [SC70-6]  (sections A,B)
R171  10K  [R0402]
R420  47K  [R-0402]
R421  10K  [R-0402]
R422  27.4K  [R-0402]
R423  10K  [R-0402]
R438  10K  [R-0402]
R514  *0R  [R-0402]
R515  *0R  [R-0402]
R516  0R  [R-0402]
R517  0R  [R-0402]
R549  10K  [R-0402]
R585  100R  [R-0402]
R586  60.4K  [R-0402]
R587  *49.9K  [R-0402]
R588  4.7K  [R-0402]
R589  4.7K  [R-0402]
R599  5.62K  [R-0402]
R600  *31.6K  [R-0402]
R612  10K  [R-0402]
R621  10K  [R-0402]
R622  1K  [R-0402]
RNTC  *10K  [R-0402]
U146  MAX17058G  [TDFN8]
U150  MAX17112  [TDFN10EP]
U182  AAT3620IWO-4.2-T1  [WFDFN-14]
U185  NC7ST32M5X  [MAC06A]
sheet P14: Front access 8 pin conn 1
C340  0.1uF  [C-0402]
C341  0.1uF  [C-0402]
C342  0.1uF  [C-0402]
C346  2.2uF  [C-0402]
C366  2.2uF  [C-0402]
C367  *2.2uF  [C-0402]
FB49  FB/3A  [L-0603]
J8  *Molex-52806-0510  [Molex_52806_0510]
J36  HDR1x8  [HDR1x8_100milSMT]
Q66  Si1016X-T1-GE3  [SOT563]  (sections A,B)
Q67  Si1016X-T1-GE3  [SOT563]  (sections A,B)
Q68  Si1016X-T1-GE3  [SOT563]  (sections A,B)
Q69  Si1016X-T1-GE3  [SOT563]  (sections A,B)
Q70  Si1016X-T1-GE3  [SOT563]  (sections A,B)
Q71  Si1016X-T1-GE3  [SOT563]  (sections A,B)
Q72  Si1016X-T1-GE3  [SOT563]  (sections A,B)
Q73  Si1016X-T1-GE3  [SOT563]  (sections A,B)
Q166  FDG6301N  [SC70-6]  (sections A,B)
Q169  FDG6301N  [SC70-6]  (sections A,B)
R347  10K  [R-0201]
R348  10K  [R-0201]
R349  10K  [R-0201]
R350  10K  [R-0201]
R351  10K  [R-0201]
R352  10K  [R-0201]
R353  10K  [R-0201]
R354  10K  [R-0201]
R355  10K  [R-0201]
R356  10K  [R-0201]
R357  10K  [R-0201]
R358  10K  [R-0201]
R359  10K  [R-0201]
R360  10K  [R-0201]
R361  10K  [R-0201]
R362  10K  [R-0201]
R393  10K  [R-0201]
R419  *10K  [R-0402]
R468  10K  [R-0201]
R469  10K  [R-0201]
R474  10K  [R-0201]
R475  10K  [R-0201]
R505  10K  [R-0201]
R510  *10K  [R-0201]
R511  10K  [R-0201]
R532  1K  [R-0402]
R533  1K  [R-0402]
R581  *0R  [R-0402]
R582  0R  [R-0402]
R634  10K  [R-0201]
R643  10K  [R-0402]
R644  1K  [R-0402]
U135  PIC16F1508  [QFN20]
U136  74HC4094  [TSSOP16]
U137  74HC4094  [TSSOP16]
U141  *RT9715EGB  [SOT23-5]
U148  *RT9715EGB  [SOT23-5]
U177  D5V0F4U6SO-7  [SC-74]
U178  D5V0F4U6SO-7  [SC-74]
U190  FPF1320  [6WLCSP]

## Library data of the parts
Q154 Q155 Q163 Q169 = NMOS-DUAL6-sc70: Desc: MOSFET 2N-CH 25V 0.22A SC70-6; Vendor: Fairchild; x: MOSFET 2N-CH 25V 0.22A SC70-6
C10 C11 = CAP_NP_0: Desc: CAP CER 18PF 50V 5% NP0 0402; Part Num: GRM1555C1H180JA01D; Vendor: Murata; mfg: Murata; mfg_pn: GRM1555C1H100JZ01D
C211 = CAP_NP_2: Desc: CAP CER 4.7UF 6.3V 20% X5R 0402; Part Num: CL05A475MQ5NRNC; Vendor: TDK; mfg: TDK; mfg_pn: C1005X7R1A104K
Q156 Q161 = FDMA1029PZ: Desc: MOSFET 2P-CH 20V 3.7A MICROFET; Vendor: Fairchild
R17 R18 R31-R35 R70 R384-R387 R617 R618 R636 R638 R642 = Res_0: Desc: RES 10K OHM 1/10W 5% 0402 SMD; Mfr: Generic; Part Num: ERJ-2GEJ103X; Vendor: Panasonic
R21 = Res_0: Desc: RES 6.04K OHM 1/10W 1% 0603 SMD; Mfr: Generic; Part Num: ERJ-3EKF6041V; Vendor: Panasonic
R22 R581 = Res_0: Desc: RES 0.0 OHM 1/10W 0402 SMD; Mfr: Generic; Part Num: ERJ-2GE0R00X; Vendor: Panasonic
R23 R24 R327 R328 R582 = Res_0: Desc: RES 0.0 OHM 1/10W 0402 SMD; Mfr: Generic; Part Num: ERJ-2GE0R00X; Vendor: Panasonic; ccc: RES 0.0 OHM 1/10W 0402 SMD
R25 = Res_0: Desc: RES 1.00M OHM 1/16W 1% 0402 SMD; Mfr: Generic; Part Num: MCR01MZPF1004; Vendor: Panasonic
R77 = R_0: Desc: RES 10K OHM 1/10W 5% 0402 SMD; Mfr: Generic; Part Num: ERJ-2GEJ103X; Vendor: Panasonic
R308 R309 R325 R326 R382 R518 R605 R608 R612 R620 R631 = Res_0: Desc: RES 10K OHM 1/10W 5% 0402 SMD; Part Num: ERJ-2GEJ103X; Vendor: Panasonic
U1 = PXA168_1: Desc: IC App Processor SOC; Part Num: 88AP166SA0-BJD2C008; Vendor: Marvell
Y1 = OSC5_1.5: Desc: CRYSTAL 26.000 MHZ 12PF SMD 3225; Part Num: 2126000A-A000-X0; Vendor: HuiJing
C320 C322 C331 C518 C519 = CAP_NP: CAP CER .10UF 10V X5R 10% 0402; Desc: CAP CER .10UF 10V X7R 0402; Distributor: Digi-Key; Distributor Part Number: 445-1265-1-ND; Manufacturer: C1005X5R1A104K; Manufacturer Part Number: CAP CER .10UF 10V X5R 10% 0402; Part Num: C1005X7R1A104K; Vendor: TDK
C321 C327 = CAP_NP: CAP CER .10UF 10V X5R 10% 0402; Desc: CAP CER 2200PF 10V 20% X7R 0402; Distributor: Digi-Key; Distributor Part Number: 445-1265-1-ND; Manufacturer: C1005X5R1A104K; Manufacturer Part Number: CAP CER .10UF 10V X5R 10% 0402; Part Num: CL05B222MP5NNNC; Vendor: Samsung
C357 C358 C517 = CAP_NP_0: Desc: CAP CER 4.7UF 10V 10% X5R 0603; OPTION: LIPO; Part Num: LMK107BJ475KA-T; Vendor: Taiyo
CM1 = CMC_3L: Desc: CHOKE COMMON MODE 800 OHM SMD; Part Num: ACM2520-801-3P-T002; Vendor: TDK
CM3 = CMC_2L_1-2_3-4: Desc: Common Mode Choke 0.38uH 31mR 2.3A; Vendor: Coilcraft
D12 D14 = DIODE_SCHOTTKY: Desc: DIODE ESD PROT 1A 100V MICROSMP; Vendor: Vishay
D32 = Diode: Desc: DIODE SCHOTTKY 30V 0.2A SOD523F; Vendor: Fairchild
D28 D39 D40 = DIODE_SCHOTTKY21: DIODE SCHOTTKY 1A 40V SMA; Desc: DIODE SCHOTTKY 10V 2A SMA; Manufacturer: Fairchild; Manufacturer_PN: SS14; Part Num: MBRA210LT3G; Vendor: ON semi
J1 = USB_MICRO_AB: CONN RCPT MICRO USB AB R/A SMD; Desc: CONN RCPT MCR USB AB SMD TH SHLL; MANUFACTURER: MOLEX; MFR PN: 0476420001; Part Num: ZX62RD-AB-5P8; Vendor: Hirose
J8 J32 = PIC_DEBUG_PAD: Desc: CONN FFC/FPC 5POS 1MM VERT T/H; Part Num: 52806-0510; Vendor: Molex
MOV1 MOV4-MOV7 MOV9 MOV10 = MOV-small: Desc: VARISTOR 6.4V 30A 0603; Part Num: B72500D50A60; Vendor: Epcos
Q177 = NMOS3: Desc: MOSFET N-CH 25V 220MA SOT-23; Vendor: FAIRCHILD
R337 R381 = Res_0: Desc: RES 47K OHM 1/10W 1% 0402 SMD; Part Num: ERJ-2RKF4702X; Vendor: Panasonic
R519 R523 R532 R533 R622 = Res_0: Desc: RES 1K OHM 1/10W 1% 0402 SMD; Mfr: Generic; Part Num: ERJ-2RKF1001X; Vendor: Panasonic
R604 R609 = RESISTOR: Desc: RES 4.7K OHM 1/10W 5% 0402 SMD; OPTION: DBG; Part Num: ERJ-2GEJ472X; Vendor: Panasonic
R607 = RESISTOR: Desc: RES 150K OHM 1/10W 5% 0402 SMD; OPTION: DBG; Part Num: ERJ-2GEJ154X; Vendor: Panasonic
R615 = RESISTOR: Desc: RES 3.3K OHM 1/10W 5% 0402 SMD; OPTION: DBG; Part Num: ERJ-2GEJ332X; Vendor: Panasonic
R616 = RESISTOR: Desc: RES 5.1M OHM 1/10W 5% 0402 SMD; OPTION: DBG; Part Num: ERJ-2GEJ515X; Vendor: Panasonic
R121 R637 R644 R647 = Res_0: Desc: RES 1K OHM 1/10W 1% 0402 SMD; Part Num: ERJ-2RKF1001X; Vendor: Panasonic
SW13 = SW_PUSHBUTTON-SPST-2_0: LT SWITCH SIDE PUSH SMD; Desc: SWITCH TACTILE SPST-NO 0.05A 12V; Manufacturer: Panasonic; Manufacturer_PN: EVQ-PUJ02K; Vendor: Tyco
TP12 TP14-TP19 TP26-TP28 = T_POINT: Desc: SMT Test Point; Part Num: NA; Vendor: Test
U159 = PIC12F508: Part Num: PIC12F508I/MC
U184 = FAN3988
U188 = 74AHCT1G08: Desc: IC GATE AND 1CH 2-INP SOT-353; Vendor: Diodes
U189 = AP2151: Desc: IC PWR SW USB 1CH 0.5A 8-MSOP; Part Num: AP2151MPG-13; Vendor: Diodes
C181 = CAP_NP_2: Desc: CAP CER 22UF 4V 20% X5R 0603; Part Num: AMK107BJ226MA-T; Vendor: Taiyo
C184 = CAP_NP_2: Desc: CAP CER .10UF 10V X7R 0402; Part Num: C1005X7R1A104K; Vendor: TDK; mfg: TDK; mfg_pn: C1005X7R1A104K
C185 = CAP_NP_2: Desc: CAP CER 10UF 10V 10% X5R 0603; Part Num: C1608X5R1A106K080AC; Vendor: TDK
C189 C192 = CAP_NP: CAP CER 10UF 10V X5R 20% 0603; Desc: CAP CER 10UF 10V 10% X5R 0603; Distributor: DIGI-KEY; Distributor_Part_Number: 587-2562-2-ND; Mfr: Taiyo Yuden; Mfr_Part_Number: LMK107BJ106MALTD; Part Num: C1608X5R1A106K080AC; Part_Number: 587-2562-2-ND; Status: PN_APPLYED; Temperature_Coefficient: X5R; Tolerance: +/-20%; Vendor: TDK; part_type: Capacitor
C190 C191 = CAP_NP: CAP CER .22UF 6.3V X5R 0201; Desc: CAP CER .22UF 6.3V X5R 0201; Distributor: DIGI-KEY; Distributor_Part_Number: 587-1819-2-ND; Mfr: Taiyo Yuden; Mfr_Part_Number: JMK063BJ224MP-F; Part Num: JMK063BJ224MP-F; Part_Number: 587-1819-2-ND; Status: PN_APPLYED; Temperature_Coefficient: X5R; Tolerance: +/-20%; Vendor: Taiyo; part_type: Capacitor; Datasheet: \\sh4-dt-609\work\CIS\datasheet\CAPACITORS\dlmk_e.pdf
C193 C194 = CAP_NP: CAP CER 22UF 4V X5R 0603; ALT_SYMBOLS: PORTABLE_CAP_0603; Desc: CAP CER 22UF 4V 20% X5R 0603; Distributor: DIGI-KEY; Distributor_Part_Number: 490-5526-2-ND; Mfr: Murata; Mfr_Part_Number: GRM188R60G226MEA0L; Part Num: AMK107BJ226MA-T; Part_Number: 490-5526-2-ND; Status: PN_APPLYED; Temperature_Coefficient: X5R; Tolerance: +/-20%; Vendor: Taiyo; part_type: Capacitor; Datasheet: \\sh4-dt-609\work\CIS\datasheet\CAPACITORS\djmk_e.pdf
C195 = CAP_NP: CAP CER 10UF 6.3V X5R 0603; Desc: CAP CER 10UF 6.3V 20% X5R 0402; Distributor: DIGI-KEY; Distributor_Part_Number: 490-3896-2-ND; Mfr: Murata; Mfr_Part_Number: GRM188R60J106ME47D; Part Num: C1005X5R0J106M050BC; Part_Number: 490-3896-2-ND; Status: PN_APPLYED; Temperature_Coefficient: X5R; Tolerance: +/-20%; Vendor: TDK; part_type: Capacitor; Datasheet: \\sh4-dt-609\work\CIS\datasheet\CAPACITORS\GRM188R60J106ME47.pdf
C196 = CAP_NP: CAP CER 1UF 10V X5R 0402; Desc: CAP CER 1UF 10V 10% X5R 0402; Distributor: Digi-Key; Distributor_Part_Number: 490-3890-2-ND; Mfr: Murata Electronics North America; Mfr_Part_Number: GRM155R61A105KE15D; Part Num: C1005X5R1A105K050BB; Part_Number: 490-3890-2-ND; Status: PN_APPLYED; Temperature_Coefficient: X5R; Tolerance: +/-10%; Vendor: TDK; ccc: CAP CER 1UF 10V 10% X5R 0402; part_type: Capacitor; Datasheet: \\sh4-dt-609\work\CIS\datasheet\CAPACITORS\GRM155R61A105KE15.pdf
C328 = CAP_NP: CAP CER 4.7UF 6.3V +/-10% X5R 0603; Desc: CAP CER 4.7UF 6.3V 10% X5R 0603; Manufacturer: Murata; Manufacturer Part Number: GRM188R60J475KE19D; Part Num: GRM188R60J475KE19D; Vendor: Murata
C329 C332 C333 = CAP_NP: CAP CER 4.7UF 6.3V +/-10% X5R 0603; Desc: CAP CER 4.7UF 10V 10% X5R 0603; Manufacturer: Murata; Manufacturer Part Number: GRM188R60J475KE19D; Part Num: LMK107BJ475KA-T; Vendor: Taiyo
C330 = CAP_NP: CAP CER 10uF 6.3V X5R +/-10% 0603; Desc: CAP CER 10UF 6.3V 20% X5R 0402; Manufacturer: Murata; Manufacturer Part Number: GRM188R60J106ME47D; Part Num: C1005X5R0J106M050BC; Vendor: TDK
FB57-FB60 = FERRITE_BEAD_0: Desc: WE-CBF SMD EMI SUPP FERRITE BEAD; Part Num: 742792602; Vendor: Wurth Electronics
L10 = INDUCTOR_0: Desc: INDUCTOR 1.0UH 2.0A 30% SMD; Part Num: FLF3215T-1R0N; Vendor: TDK
L11 = INDUCTOR: Desc: INDUCTOR POWER 1.2UH 3.8A SMD; Mfr: Toko; Mfr_Part_Number: NLC565050T-1R2K-P; Part Num: VLC5020T-1R2N; Part_Number: NLC565050T-1R2K-P; Status: PN_APPLYED; Vendor: TDK; part_type: Inductor; Datasheet: \\SH4-DT-609\WORK\CIS\datasheet\FDSD0412_Sept2011.pdf
L12 = INDUCTOR: INDUCTOR 1.5uH 20%, max thermal current 2.05A SMD; ALT_SYMBOLS: INDUCTOR_3012_Large; Desc: FIXED IND 1.5UH 2.2A 72 MOHM SMD; Mfr: Toko; Mfr_Part_Number: MDT2520-CN1R5M; Part Num: IFSC1008ABER1R5M01; Part_Number: IFSC1008ABER1R5M01; Status: PN_APPLYED; Vendor: Vishay; part_type: Inductor; Datasheet: \\SH4-DT-609\WORK\CIS\datasheet\mdt2520_cn.pdf
L35 = INDUCTOR: MDT2520-CN Type,1.0uH,85mΩ，H=1.2mm,L=2.5mm,W=2.0mm; Desc: INDUCTOR POWER 1UH 2.6A SMD; Manufacturer: TOKO; Manufacturer Part Number: MDT2520-CN1R0M; Part Num: IFSC1008ABER1R0M01; Vendor: Vishay
R109 R112 = R_0: Desc: RES 0.0 OHM 1/10W 0402 SMD; Mfr: Generic; Part Num: ERJ-2GE0R00X; Vendor: Panasonic
R110 R111 R116 R120 = R_0: Desc: RES 100K OHM 1/16W 5% 0402 SMD; Mfr: Generic; Part Num: CRCW0402100KJNED; Vendor: Vishay
R113 = R_0: Desc: RES 51K OHM 1/10W 5% 0402 SMD; Mfr: Generic; Part Num: ERJ-2GEJ513X; Vendor: Panasonic
R114 = R_0: Desc: RES SMD 30K OHM 5% 1/10W 0402; Mfr: Generic; Part Num: ERJ-2GEJ303X; Vendor: Panasonic
R117 = R_0: Desc: RES 10 OHM 1/10W 5% 0402 SMD; Mfr: Generic; Part Num: ERJ-2GEJ100X; Vendor: Panasonic
R118 = Res_0: Desc: RES 1K OHM 1/10W 1% 0402 SMD; Mfr: Generic; Part Num: ERJ-2RKF1001X; Vendor: Panasonic; d: RES 1K OHM 1/10W 1% 0402 SMD
R122 = R: RES 10.0 OHM 1/16W 1% 0402 SMD; Desc: RES 10 OHM 1/10W 5% 0402 SMD; Distributor: Digikey; Distributor_Part_Number: 311-10.0LRTR-ND; Mfr: Yageo; Mfr_Part_Number: RC0402FR-0710RL; Part Num: ERJ-2GEJ100X; Part_Number: 311-10.0LRTR-ND; Power: 0.063W, 1/16W; Status: PN_APPLYED; Temperature_Coefficient: +/-200ppm/C; Tolerance: +/-1%; Vendor: Panasonic; part_type: Resistor; Datasheet: \\sh4-dt-609\work\CIS\datasheet\RESISTORS\PYu-RC0402_51_RoHS_L_6.pdf
R134 R389 = Res_0: Desc: RES 100K OHM 1/16W 5% 0402 SMD; Part Num: CRCW0402100KJNED; Vendor: Vishay
R388 = RES_169K_1p_1: RES 100K OHM 1/10W 5% 0603 SMD; Desc: RES 100K OHM 1/16W 5% 0402 SMD; Distributor: Digi-Key; Distributor Part Number: P100KGTR-ND; Distributor_Part_Number: P100KGTR-ND; Manufacturer: Panasonic - ECG; Manufacturer Part Number: ERJ-3GEYJ104V; Part Num: CRCW0402100KJNED; Percent: 5%; Tolerance: 5%; Vendor: Vishay; Wattage: 1/10W
R640 R641 = Res_0: Desc: RES 1K OHM 1/10W 1% 0402 SMD; Part Num: ERJ-2RKF1001X; Vendor: Vishay
U16 = 88PG867: Desc: IC Power, Dual 3A/1A buck; Part Num: 88PG867-HB0-NNY2C00; Vendor: Marvell
U133 = 88PG8111-1: Desc: IC power, 500mA buck 50mA LDO; Part Num: 88PG8211A2-NXS2C000; Vendor: Marvell
VR1 = 88PG818_0: Desc: IC Power Switching; Part Num: 88PG839-A1-NAE2C000; Vendor: Marvell
C103 = CAP_NP_0: CAP CER 0.10uF 6.3V X5R 0201; Desc: CAP CER .10UF 10V X7R 0402; Manufacturer: Taiyo Yuden; Manufacturer_PN: JMK063BJ104KP-F; OPTION: LIPO; Part Num: C1005X7R1A104K; Vendor: TDK
C351 C509 = CAP_NP_0: Desc: CAP CER 1UF 10V 10% X5R 0402; OPTION: LIPO; Part Num: C1005X5R1A105K050BB; Vendor: TDK; ccc: CAP CER 1UF 10V 10% X5R 0402
C352 C353 C508 = CAP_NP_0: Desc: CAP CER 10UF 10V 10% X5R 0603; OPTION: LIPO; Part Num: C1608X5R1A106K080AC; Vendor: TDK
C354 C361 = CAP_NP_0: Desc: CAP CER 560PF 25V 5% NP0 0402; OPTION: LIPO; Part Num: C1005C0G1E561J; Vendor: TDK
C360 = CAP_NP_0: Desc: CAP CER 3300PF 10V 5% SL 0402; OPTION: LIPO; Part Num: C1005SL1A332J; Vendor: TDK
C510 C512 C513 C516 = CAP_NP_1: Desc: CAP CER .10UF 10V X7R 0402; Part Num: C1005X7R1A104K; Vendor: TDK
C511 = CAP_NP_2: Desc: CAP CER 22UF 10V 10% X5R 1210; Part Num: LMK325BJ226KMHT; Vendor: Taiyo
J50 = CON3: Desc: CONN HEADER PH SIDE 3POS 2MM SMD; Part Num: S3B-PH-SM4-TB(LF)(SN); Vendor: JST
L36 = IND_SMALL: Desc: INDUCTOR POWER 2.7UH 2.43A 0403; OPTION: LIPO; Part Num: SDR0403-2R7ML; Vendor: Bourns
L37 = IND_SMALL: Desc: FIXED IND 4.7UH 1.4A 120 MOHM; OPTION: LIPO; Part Num: NRS5014T4R7NMGGV; Vendor: Taiyo Yuden
R171 = R_0: RES 10.0K OHM 1/10W 1% 0402 SMD; Desc: RES 10K OHM 1/10W 5% 0402 SMD; Manufacturer: Panasonic - ECG; Manufacturer_PN: ERJ-2RKF1002X; OPTION: LIPO; Part Num: ERJ-2GEJ103X; Vendor: Panasonic
R420 = Res_0: Desc: RES 47K OHM 1/10W 1% 0402 SMD; OPTION: LIPO; Part Num: ERJ-2RKF4702X; Vendor: Panasonic
R421 R423 R438 R549 R621 = Res_0: Desc: RES 10K OHM 1/10W 5% 0402 SMD; OPTION: LIPO; Part Num: ERJ-2GEJ103X; Vendor: Panasonic
R422 = Res_0: Desc: RES 27.4K OHM 1/10W 1% 0402 SMD; OPTION: LIPO; Part Num: ERJ-2RKF2742X; Vendor: Panasonic
R514-R517 = Res_0: Desc: RES 0.0 OHM 1/10W 0402 SMD; Part Num: ERJ-2GE0R00X; Vendor: Panasonic
R585 = RESISTOR: Desc: RES 100 OHM 1/10W 1% 0402 SMD; OPTION: DBG; Part Num: ERJ-2RKF1000X; Vendor: Panasonic
R586 = Res_0: Desc: RES 60.4K OHM 1/10W 1% 0402 SMD; Mfr: Generic; Part Num: ERJ-2RKF6042X; Vendor: Panasonic
R587 = Res_0: Desc: RES 49.9K OHM 1/10W 1% 0402 SMD; OPTION: LIPO; Part Num: ERJ-2RKF4992X; Vendor: Panasonic; d: RES 49.9K OHM 1/10W 1% 0402 SMD
R588 R589 = Res_0: Desc: RES 4.7K OHM 1/10W 5% 0402 SMD; Mfr: Generic; Part Num: ERJ-2GEJ472X; Vendor: Panasonic
R599 = Res_0: Desc: RES 5.62K OHM 1/10W 1% 0402 SMD; OPTION: LIPO; Part Num: ERJ-2RKF5621X; Vendor: Panasonic; d: RES 10K OHM 1/10W 1% 0402 SMD
R600 = Res_0: Desc: RES 31.6K OHM 1/10W 1% 0402 SMD; OPTION: LIPO; Part Num: ERJ-2RKF3162X; Vendor: Panasonic; d: RES 31.6K OHM 1/10W 1% 0402 SMD
RNTC = Thermistor: Desc: THERMISTOR NTC 10K OHM 5% 0402; Part Num: ERT-J0EG103FA; Vendor: Panasonic
U146 = MAX17058TDFN
U150 = MAX17112
U182 = AAT3620IWO-4.2-T1_1: Desc: 1 CELL LI+ SWITCH MODE CHARGER; Vendor: Skyworks
U185 = NC7S32P5X: Desc: IC GATE OR 1CH 2-INP SOT-23-5; Vendor: Fairchild
C340-C342 = CAPACITOR_NON-POL: Desc: CAP CER .10UF 10V X7R 0402; OPTION: DBG; Part Num: C1005X7R1A104K; Vendor: TDK
C346 C366 C367 = CAP_NP_2: Desc: CAP CER 2.2UF 10V 10% X5R 0402; Part Num: C1005X5R1A225K; Vendor: TDK
FB49 = FERRITE_BEAD_0: Desc: FERRITE CHIP 120 OHM 3000MA 0603; Part Num: BLM18KG121TN1; Vendor: Murata
J36 = CON8: Desc: CONN HEADER FEMALE 8POS .1" GOLD; Part Num: SSM-108-F-SV; Vendor: Samtec
Q66-Q73 = CMOS-DUAL: Desc: MOSFET N/P-CH 20V 600/350 SC89-6; Vendor: Vishay
Q166 = NMOS-DUAL6-sc70: Desc: MOSFET 2N-CH 25V 0.22A SC70-6; Vendor: Fairchild
R347-R362 R419 R643 = R_0: Desc: RES 10K OHM 1/20W 5% 0201 SMD; Mfr: Generic; Part Num: ERJ-1GEJ103C; Vendor: Panasonic
R393 = R_0: Desc: RES 10K OHM 1/20W 5% 0201 SMD; Mfr: Generic; Part Num: ERJ-1GEJ103C; Vendor: Panasonic; d: RES 1K OHM 1/10W 1% 0402 SMD
R468 R469 R505 R510 R511 R634 = Res_0: Desc: RES 10K OHM 1/20W 5% 0201 SMD; Part Num: ERJ-1GEJ103C; Vendor: Panasonic
R474 R475 = Res_0: Desc: RES 10K OHM 1/20W 5% 0201 SMD; Mfr: Generic; Part Num: ERJ-1GEJ103C; Vendor: Panasonic
U135 = PIC16F1508QFN: Vendor: microchip
U136 U137 = 74HC4094
U141 U148 = RT9517SOT23-5: Desc: IC PWR SW USB 1.1A SOT23-5; Part Num: RT9715EGB; Vendor: Richtek
U177 U178 = CM1293A: Desc: TVS DIODE 5.5VWM 12VC SOT26; Vendor: Diodes
U190 = FPF1321

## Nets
FLX1_3VENH/5VENL: Q169.2(G) R419.2 R634.1 U148.4(EN/~{EN}) U190.B1(SEL) ; also on sheet 1
GND: C10.2 C11.2 C103.2 C181.2 C184.2 C185.2 C189.1 C190.1 C191.1 C192.2 C193.2 C194.2 C195.1 C196.1 C320.2 C322.2 C328.1 C329.1 C330.1 C331.2 C332.1 C333.1 C340.2 C341.2 C342.2 C346.2 C351.2 C352.2 C353.2 C354.2 C357.2 C358.2 C360.2 C361.2 C366.2 C367.2 C508.1 C509.2 C510.2 C511.2 C512.2 C513.2 C516.2 C517.2 C518.2 C519.2 CM3.4(IN2) J8.3(VSS) J32.3(VSS) J50.2 MOV4.1 MOV5.1 MOV6.1 MOV7.1 MOV9.1 MOV10.1 Q66.1(S) Q67.1(S) Q68.1(S) Q69.1(S) Q70.1(S) Q71.1(S) Q72.1(S) Q73.1(S) Q155.1(S) Q163.1(S) Q163.4(S) Q169.1(S) Q177.S R18.2 R21.2 R22.1 R23.1 R24.1 R70.2 R77.2 R110.2 R112.2 R113.2 R114.2 R116.1 R347.1 R349.1 R351.1 R353.1 R355.1 R357.1 R359.1 R361.1 R384.1 R386.2 R389.2 R419.1 R421.2 R438.2 R505.1 R511.2 R549.2 R586.2 R587.2 R600.2 R605.1 R608.1 R616.2 R617.2 R636.2 R638.2 R642.2 R643.1 R647.1 RNTC.1(A) SW13.1 SW13.3 TP27.1(TP) TP28.1(TP) U16.1(PGND) U16.2(PGND1_1) U16.7(PGND1_2) U16.8(PGND) U16.12(PGND) U16.13(PGND2_1) U16.20(SGND) U16.24(PGND) U16.EP U133.2(SGND) U133.5(PGND2) U133.12(SGND12) U133.21(PGND) U135.17(VSS) U135.EP(VSS) U136.8(GND) U137.8(GND) U141.2(GND) U146.1(CTG) U146.4(GND) U146.6(QSTRT) U146.PAD U148.2(GND) U150.4(GND) U150.5(GND) U150.EP(PAD) U159.8(VSS) U159.EP(PAD) U177.2(NV) U178.2(NV) U182.2(PGND) U182.3(GND) U182.15(EP) U184.4(GND) U185.3(Gnd) U188.3(Gnd) U189.1(GND) U190.C1(GND) VR1.4(SGND) VR1.13(PGND) ; also on sheet 1 2 3 4 5 6 7 8 18 19
GND_EN1: Q66.2(G) R347.2 U137.14(QP4)
GND_EN2: Q67.2(G) R349.2 U137.13(QP5)
GND_EN3: Q68.2(G) R351.2 U137.12(QP6)
GND_EN4: Q69.2(G) R353.2 U137.11(QP7)
GND_EN5: Q70.2(G) R355.2 U136.14(QP4)
GND_EN6: Q71.2(G) R357.2 U136.13(QP5)
GND_EN7: Q72.2(G) R359.2 U136.12(QP6)
GND_EN8: Q73.2(G) R361.2 U136.11(QP7)
GND_OTG: CM3.3(OUT2) D12.1(ANODE) D14.1(ANODE) J1.5(GND) J1.T3(TAB) J1.T4(TAB) J1.T5(TAB) J1.T6(TAB) MOV1.1
V1P5_DDR: FB60.2 MOV5.2 TP12.1(TP) ; also on sheet 2 5
V1P8: FB59.1 MOV6.2 TP16.1(TP) ; also on sheet 2 4
V3P3: FB57.2 Q154.2(G) Q154.5(G) Q156.4(S2) Q166.2(G) Q166.5(G) R17.1 R31.1 R32.1 R33.1 R34.1 R35.1 R171.1 R325.2 R326.2 R393.2 R423.1 R468.2 R469.2 R588.2 R589.2 R620.1 R634.2 R642.1 R644.1 TP14.1(TP) ; also on sheet 1 2 3 4 5 6 7 8 18 19
V3P3_USB_A: C211.1 ; also on sheet 2
V3P3AEXP: U148.5(VIN) U190.C2(VINB) ; also on sheet 18 19
VBAT_H: Q163.5(G) R549.1 R612.2
VBAT_L: Q163.3(D) R423.2 U1.D13(MFP25)
VBUS_OTG: C517.1 C519.1 CM3.1(IN1) D40.2(A) R604.1 R609.1 TP19.1(TP) U184.1(VBUS) U188.1(A) U189.6(VOUT) U189.7(VOUT)
VBUS_OTG_CONN: CM3.2(OUT1) J1.1(VBUS) MOV1.2
VBUS_SER: D39.2(A) ; also on sheet 8
VCC_CHRG: C509.1 R585.1 R599.1 U182.4(VCC)
VCC_FLEX1: C340.1 C341.1 C342.1 C346.1 C366.1 FB49.2 J8.2(VDD) Q66.4(S) Q67.4(S) Q68.4(S) Q69.4(S) Q70.4(S) Q71.4(S) Q72.4(S) Q73.4(S) R348.1 R350.1 R352.1 R354.1 R356.1 R358.1 R360.1 R362.1 R474.1 R475.1 R510.2 U135.18(VDD) U136.16(VCC) U137.16(VCC) ; also on sheet 7
VCC_FLEX1S: C367.1 FB49.1 U141.1(VOUT) U148.1(VOUT) U190.B2(VOUT)
VIN: C352.1 C353.1 C508.2 C510.1 C516.1 C518.1 D28.1(K) D32.1(C1) D39.1(K) D40.1(K) MOV4.2 Q161.1(S1) Q161.4(S2) R337.1 R381.1 R422.1 R585.2 R615.1 TP18.1(TP) U182.1(VPIN) U185.5(Vcc) U188.5(Vcc) U189.2(VIN) U189.3(VIN) ; also on sheet 7
AP_ISET: R21.1 U1.R17(A_ISET(USB))
AP_JTAG_SEL: Q156.3(D2) Q156.8(D2a) R17.2 R18.1 U1.N2(JTAG_SEL_(FN0))
AP_PRI_TCK: U1.M2(PRI_TCK_(FN0)) ; also on sheet 8
AP_PRI_TDI: U1.L4(PRI_TDI_(FN0)) ; also on sheet 8
AP_PRI_TDO: U1.M3(PRI_TDO_(FN0)) ; also on sheet 8
AP_PRI_TMS: U1.M1(PRI_TMS_(FN0)) ; also on sheet 8
AP_TRST_N: U1.M4(TRST_N_(FN0)) ; also on sheet 8
AP_UART2_RX: U1.A2(MFP88(UART2_RTX_D)_(FN2/3)) ; also on sheet 6 8
AP_UART2_TX: U1.D4(MFP89(UART2_TRX_D)_(FN2/3)) ; also on sheet 6 8
AUDIO_ADCDAT: U1.J3(MFP116(SSP1_RTXD)_(FN2)) ; also on sheet 4
AUDIO_BCLK: U1.J4(MFP115(SSP1_CLK)_(FN1)) ; also on sheet 4
AUDIO_DACDAT: U1.J2(MFP117(SSP1_RTXD)_(FN2)) ; also on sheet 4
AUDIO_LRCK: U1.H1(MFP114(SSP1_FRM)_(FN1)) ; also on sheet 4
AUDIO_MCLK: U1.H2(MFP113(SSP_SYSCLK)_(FN6)) ; also on sheet 4
BSTEN_H/CHRGEN_L: C360.1 Q163.6(D) R519.1 R622.1 U150.9(\~{SHD}N)
BSTEN_L: Q163.2(G) R438.1 R621.1
CE156ON_L: U1.K18(MFP43_(GPI_AU_JD#)) ; also on sheet 4
CHGR_ENH: R621.2 U182.5(EN) U185.4(Y)
CP1: U135.5(RC6) U136.3(CP) U137.3(CP)
D_1_4: U135.3(RC4) U137.2(D)
D_5_8: U135.2(RC5) U136.2(D)
EN2A: R121.1 R636.1 R640.1 U16.23(EN2)
EN2B: R637.2 R638.1 R641.1 U133.11(EN2)
ENLDO: R386.1 U133.16(ENLDO)
FLX1_OC_L: U141.3(~{FLG}) U148.3(~{FLG}) ; also on sheet 1
GG_SCL: R515.1 R516.1 U146.7(SCL)
GG_SDA: R514.1 R517.1 U146.8(SDA)
GPIO_PWR_BTN: Q154.1(S) R325.1 R327.1 U1.G17(MFP53_(GPO_SLP_GNT#)_(FN0))
GPIO_PWR_CLK: Q154.4(S) R326.1 R328.1 U1.G18(MFP52_(GPI_SLP_REQ#)_(FN0))
HIB_EN: R382.2 U159.3(GP4)
ICSPCLK: J32.5(PGC) R518.2 R519.2 U159.6(GP1/ICSPC)
ICSPCLK1: J8.5(PGC) R532.2 U135.15(RA1/AN1) ; also on sheet 7
ICSPDAT: J32.4(PGD) R523.1 U159.7(GP0/ICSPD)
ICSPDAT1: J8.4(PGD) R533.2 U135.16(RA0/AN0) ; also on sheet 7
INT_PCONN: U135.7(RB7) ; also on sheet 18 19
INT_SCL1: Q166.3(D) R474.2 U135.8(RB6/SCL)
INT_SCL3: Q166.4(S) R468.1 ; also on sheet 18 19
INT_SDA1: Q166.6(D) R475.2 U135.10(RB4/SDA)
INT_SDA3: Q166.1(S) R469.1 ; also on sheet 18 19
LOW_BATT: R171.2 R523.2 U1.A16(MFP19_(GPI_TSC_IRQ#)) U146.5(ALRT)
MFP37: U1.L15(MFP37_(CCIC_DAT7)_(FN4)) ; also on sheet 18
MFP38: U1.L16(MFP38_(CCIC_DAT6)_(FN4)) ; also on sheet 18
MFP39: U1.M15(MFP39_(CCIC_DAT5)_(FN4)) ; also on sheet 18
MFP40: U1.K15(MFP40_(CCIC_DAT4)_(FN4)) ; also on sheet 18
MFP41: U1.K16(MFP41_(CCIC_DAT3)_(FN4)) ; also on sheet 18
MFP42: U1.K17(MFP42_(CCIC_DAT2)_(FN4)) ; also on sheet 18
MFP44: U1.J15(MFP44_(CCIC_DAT1)_(FN4)) ; also on sheet 18
MFP45: U1.J16(MFP45_(CCIC_DAT0)_(FN4)) ; also on sheet 18
MFP46: U1.J17(MFP46_(CCIC_VSYNC)_(FN4)) ; also on sheet 18
MFP48: U1.H18(MFP48_(CCIC_HSYNC)_(FN4)) ; also on sheet 18
MFP49: U1.H17(MFP49_(GPI_SD_REQ#)_(FN0)) ; also on sheet 18
MFP50: U1.H16(MFP50_(CCIC_VCLK)_(FN4)) ; also on sheet 18
MFP51: U1.H15(MFP51_(GPO_SD_GNT#)_(FN0)) ; also on sheet 18
MFP54: U1.G16(MFP54_(CCIC_MCLK)_(FN4)) ; also on sheet 18
MFP55: U1.G15(MFP55_(CCIC_PCLK)_(FN4)) ; also on sheet 18
MFP90: U1.B2(MFP90(MMC2_DAT3)_(FN1)) ; also on sheet 6 18
MFP91: U1.C3(MFP91(MMC2_DAT2)_(FN1)) ; also on sheet 6 18
MFP92: U1.A1(MFP92(MMC2_DAT1)_(FN1)) ; also on sheet 6 18
MFP93: U1.B1(MFP93(MMC2_DAT0)_(FN1)) ; also on sheet 6 18
MFP95: U1.C2(MFP95(MMC2_CLK)_(FN1)) ; also on sheet 18
MFP96_PWM3: U1.E4(MFP96_(GPIO)_(FN0)) ; also on sheet 18
MFP97_PWM2: U1.C1(MFP97_(PWM2)_(FN1)) ; also on sheet 18
MFP104_PWM4: U1.E1(MFP104_(PWR_CTL_WIFI)) ; also on sheet 18
MFP_SCL: R32.2 R516.2 U1.F3(MFP103(I2C_SCL)_(FN1)) ; also on sheet 4 6 18
MFP_SDA: R31.2 R517.2 U1.E2(MFP102(I2C_SDA)_(FN1)) ; also on sheet 4 6 18
MODE2: R384.2 U133.4(MODE2)
OE1: R505.2 U135.19(RA5) U136.15(OE) U137.15(OE)
OTG_CHGR33_L: Q177.D R620.2 ; also on sheet 1
OTG_CHGR_H: R607.2 U185.2(B) U188.4(Y)
OTG_OCL: U1.K3(MFP121) U189.5(FLG)
OTG_PEN: R647.2 U1.J1(MFP118) U189.4(EN)
PCA_RST: U1.J18(MFP47) ; also on sheet 18
PIN1: J36.1 Q66.3(D) Q66.6(D) R533.1 U177.1(CH1) ; also on sheet 18
PIN2: J36.2 Q67.3(D) Q67.6(D) R532.1 U177.3(CH2) ; also on sheet 18
PIN3: J36.3 Q68.3(D) Q68.6(D) U135.14(RA2/AN2) U177.4(CH3) ; also on sheet 18
PIN4: J36.4 Q69.3(D) Q69.6(D) U135.20(RA4/AN3) U177.6(CH4) ; also on sheet 18
PIN5: J36.5 Q70.3(D) Q70.6(D) U135.13(RC0/AN4) U178.6(CH4) ; also on sheet 18
PIN6: J36.6 Q71.3(D) Q71.6(D) U135.12(RC1/AN5) U178.4(CH3) ; also on sheet 18
PIN7: J36.7 Q72.3(D) Q72.6(D) U135.11(RC2/AN6) U178.3(CH2) ; also on sheet 18
PIN8: J36.8 Q73.3(D) Q73.6(D) U135.4(RC3/AN7) U178.1(CH1) ; also on sheet 18
PWR_BTN: C322.1 J32.1(VPP) Q154.6(D) R309.2 R327.2 SW13.2 SW13.4 U159.4(GP3/MCLR)
PWR_CLK: Q154.3(D) R328.2 R631.2 U159.5(GP2)
PWR_EN1: Q66.5(G) R348.2 U137.4(QP0)
PWR_EN2: Q67.5(G) R350.2 U137.5(QP1)
PWR_EN3: Q68.5(G) R352.2 U137.6(QP2)
PWR_EN4: Q69.5(G) R354.2 U137.7(QP3)
PWR_EN5: Q70.5(G) R356.2 U136.4(QP0)
PWR_EN6: Q71.5(G) R358.2 U136.5(QP1)
PWR_EN7: Q72.5(G) R360.2 U136.6(QP2)
PWR_EN8: Q73.5(G) R362.2 U136.7(QP3)
PWR_SCL: R33.2 R515.2 U1.L2(PWR_SCL_(FN0)) U16.16(SCL)
PWR_SDA: R34.2 R514.2 U1.L3(PWR_SDA_(FN0)) U16.17(SDA)
PXTAL_IN: C11.1 R25.1 U1.R18(PXTAL_IN_(FN0)) Y1.3(OUT)
PXTAL_OUT: C10.1 R25.2 U1.T18(PXTAL_OUT_(FN0)) Y1.1(IN)
RST_AP#: Q155.6(D) Q156.5(G2) R35.2 R618.2 U1.L1(RESET_IN#_(FN0)) ; also on sheet 8
SDCARD_DET: U1.A3(MFP86_(CD)_(FN0)) ; also on sheet 5
SDI: R389.1 U133.15(SDI)
SLEEPn: R134.1 U16.22(SLEEPn)
SPI_CLK: U1.H4(MFP111(SSP2_CLK)_(FN4)) ; also on sheet 5
SPI_FRM: U1.H3(MFP112(SSP2_FRM)_(FN4)) ; also on sheet 5
SPI_NOR_ON: U1.G1(MFP110_(CS#_SPI_BOOT)) ; also on sheet 5
SPI_RXD: U1.G4(MFP107(SSP2_RXD)_(FN4)) ; also on sheet 5
SPI_TXD: U1.G3(MFP108(SSP2_TXD)_(FN4)) ; also on sheet 5
STAT1: R588.1 U182.9(STAT1) ; also on sheet 1
STAT2: R589.1 U182.8(STAT2) ; also on sheet 1
STR1: U135.6(RC7) U136.1(STR) U137.1(STR)
SW1: L11.2 U16.3(SW1_1) U16.6(SW1_2)
SW2: L12.2 U16.14(SW2)
SW3: L10.1 VR1.6(SW) ; also on sheet 7
SYS_EN: R308.2 U159.2(GP5)
UART2_CBUS0: U185.1(A) ; also on sheet 8
UART3_RTX: U1.E3(MFP99(UART3_RTX)_(FN2/FN3)) ; also on sheet 18
UART3_TRX: U1.D2(MFP98(UART3_TRX)_(FN2/FN3)) ; also on sheet 18
USB_C_ID: CM1.1(IN1) R608.2 R609.2 U1.L17(USBC_ID_(FN0))
USB_C_VBUS: R604.2 R605.2 U1.P17(USBC_VBUS_DET_(FN0))
USB_CON_D+: CM1.5(IN5) D12.2(CATHODE) J1.3(D+)
USB_CON_D-: CM1.4(IN2) D14.2(CATHODE) J1.2(D-)
USBC_DM: CM1.3(OUT2) R616.1 U1.N18(USBC_D-_(FN0)) U184.2(D-)
USBC_DP: CM1.2(OUT1) R615.2 U1.N17(USBC_D+_(FN0)) U184.3(D+)
V_MBAT: C103.1 C357.1 C358.1 C511.1 C512.1 J50.1 J50.3 L36.1 MOV10.2 R612.1 R622.2 U146.2(CELL) U146.3(VDD) U150.8(IN) U182.12(BAT)
VCORE: FB58.1 MOV7.2 TP15.1(TP) ; also on sheet 2 3
VOUT1: C193.1 C194.1 FB58.2 L11.1 U16.10(FB1)
VOUT2: C195.2 FB57.1 L12.1 U16.11(FB2)
VPICSW: C320.1 D32.2(A) J32.2(VDD) R309.1 R518.1 R631.1 U159.1(VDD)
VPP_PIC1: R581.1 R582.1 U135.1(RA3)
VPP_PIC1a: R582.2 ; also on sheet 7
VPP_PIC1b: J8.1(VPP) R581.2
VR19_OTF: R109.1 R110.1 VR1.1(OTF)
VR19_PFM: R111.1 R112.1 VR1.2(PFM)
VR19_PGOOD: R70.1 R118.1 U16.9(EN1) VR1.8(PGOOD)
VR19_PSET: R114.1 VR1.12(PSET)
VR19_SDI: R116.2 VR1.10(SHDN/SDI)
VR19_SVIN: C184.1 R109.2 R111.2 R117.2 VR1.9(SVIN)
VR19_VSET: R113.1 VR1.11(VSET)
VSYS: C185.1 C189.2 C190.2 C191.2 C192.1 C321.1 C329.2 C331.1 C332.2 C333.2 MOV9.2 Q161.6(D1) Q161.7(D1a) R117.1 R120.2 R122.2 R134.2 R385.2 R387.2 R388.2 R640.2 R641.2 TP17.1(TP) U16.4(PVIN1_1) U16.5(PVIN1_2) U16.15(PVIN2) U133.1(SVIN) U133.7(PVIN2) U133.20(VINLDO) U141.5(VIN) U177.5(VP) U178.5(VP) U190.A2(VINA) VR1.7(PVIN) ; also on sheet 2 3 6 18 19
VSYS_HIB: C327.1 Q161.3(D2) Q161.8(D2a) R118.2 R121.2 R637.1 ; also on sheet 4
WLAN_IRQ: U1.F2(MFP105_(PWR_CTL_SD))
WLAN_PDn: U1.F1(MFP106_(PWR_CTL_USB)) ; also on sheet 3
WLAN_SD0: U1.B13(MFP30(MMC4_DAT0)_(FN1)) ; also on sheet 3
WLAN_SD1: U1.A13(MFP31(MMC4_DAT1)_(FN1)) ; also on sheet 3
WLAN_SD2: U1.D12(MFP32(MMC4_DAT2)_(FN1)) ; also on sheet 3
WLAN_SD3: U1.B12(MFP33(MMC4_DAT3)_(FN1)) ; also on sheet 3
WLAN_SDCLK: U1.A14(MFP29(MMC4_CLK)_(FN1)) ; also on sheet 3
WLAN_SDCMD: U1.B14(MFP28(MMC4_CMD)_(FN1)) ; also on sheet 3
N31000602: R22.2 U1.C15(MFP20_(FN0))
N35039659: R23.2 U1.F4(MFP100_(FN0))
N40156337: R24.2 U1.D1(MFP101_(FN0))
N40457134: C181.1 FB60.1 L10.2 VR1.5(FB)
N41772500: C196.2 R122.1 U16.21(SVIN)
N41911325: R120.1 VR1.3(EN)
N42148910: C211.2 Q155.2(G) R77.1
N42789231: C321.2 Q161.2(G1) R308.1 R337.2
N42789715: C327.2 Q161.5(G2) R381.2 R382.1
N42792074: R385.1 U133.18(MODE1)
N42792088: R387.1 U133.17(SLEEPn)
N42792186: C330.2 FB59.2 L35.1 U133.3(FB2)
N42792204: L35.2 U133.6(SW2)
N42792276: C328.2 U133.19(VLDO)
N42792288: R388.1 U133.14(SS_DONE)
N42898321: Q169.6(D) R393.1 U141.4(EN/~{EN})
N42945467: C351.1 U150.3(VL)
N42945743: D28.2(A) L36.2 U150.6(LX1) U150.7(LX2)
N42945993: R421.1 R422.2 U150.2(FB)
N42946021: R420.1 U150.1(COMP)
N42946045: C354.1 R420.2
N42946061: C361.1 U150.10(SS)
N43191810: CM1.6(IN6) J1.4(ID)
N43246894: R510.1 R511.1 U135.9(RB5)
N43761495: L37.1 U182.14(LX)
N43761498: L37.2 U182.13(CS)
N43762966: C513.1 U182.7(CT)
N43763114: R586.1 U182.6(ISET)
N43763982: R587.1 U182.10(TERM)
N43785355: R599.2 R600.1 RNTC.2(B) U182.11(TS)
N43899577: TP26.1(TP) U184.5(Flag2)
N43940048: R617.1 R618.1 U1.N3(EXT_WAKEUP)
N44095591: Q177.G R607.1
N44095597: U184.6(Flag1) U188.2(B)
N44347490: R643.2 R644.2 U190.A1(EN)

Not connected (* = marked no-connect by the designer): U1 B3(MFP87_(WP)_(FN0))* D3(MFP94(MMC2_CMD)_(FN1))* D14(MFP23_(GPO_UART/SD#)) G2(MFP109_(GPI_GSENSOR_INT)_(FN0)) K1(MFP119)* K2(MFP120)* K4(MFP122_(USB_OC#)_(FN0))* M17(USBH_D+_(FN0))* M18(USBH_D-_(FN0))*; U16 18(NC_4)* 19(NC_5)*; U133 8(NC8)* 9(NC9)* 10(NC10)* 13(NC13)*; U136 9(QS1) 10(QS2); U137 9(QS1) 10(QS2); U189 8(NC)*; Y1 2(NC1)* 4(NC2)*

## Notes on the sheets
sheet 9
- K4R5.2 Circuit changes from K4R5.1
  - replace TDK CMC with Coil Craft
- K4R5.1 Circuit changes from K4R4
  - fix sleep clock power feed
  - stuffing change for OTG detect, codec power
- K4R4.x Functional changes from K4R3.3
  - disable charger temp sensing
  - added mini USB indicators
  - modified micro USB detection to check VBUS
  - replace wifi with BLE enabled part
- K4R5 Circuit changes from K4R4
  - P06: replace azurewave wifi with AW-CH387
- K4R3.4 Functional changes from K4R3.3
  - disable charger temp sensing
  - added mini USB indicators
  - modified micro USB detection to check VBUS
- K4R4 Circuit changes from K4R3.3
  - P2: mini USB power+charger flag added
  - P4: new pmos, V1P8_OSC sequence fix
  - P7: ESD diodes spkrs,microphone,
  - P10: ESD for microUSB, PWRCLK pull up added
  - P12: ESD for miniUSB, VSYS, disable thermistor, reconnect broken VIN to VSYS_IN,
         fix U185 Part Number to footprint mismatch
  - P13: added isolation for FTDI, value change for FTDI reset
sheet 10
- silkscreen TP17:VSYS
- System Power supplies
- R113 Rvset
  51K = 1.5v
  R114 Rpset when R109 populated
  30K = -5.0%
- Default to PFM mode
- silkscreen TP16:V1P8
- silkscreen TP12:V1P5_DDR
- Mode1:H Mode2:L Cout2=1.8V:1.8V
- SDI = low enable EN= high enable
- slikscreen TP27: GND
- DDR3 1.5V
- WIFI & other 1.8V
- ECO K4R5 : replace 0R with FB
- VCORE 1.0V
- SYSTEM 3.3V
- silkscreen:VCORE
- silkscreen Tp14:V3P3
- Connect two ground in one point at the (-) terminal
  of the output capacitors in layout.
- silkscreen TP28:GND
- I2C linux address: 0x18
sheet 12
- This Design is given "AS IS" without warranty of any kind,
  either expressed or implied.
sheet 13
- Mod: replace 10mR with diodes to isolate two vbus
  during plug in
- Power Button
- Power Input
- While off - pressing will turn unit on
  while on - momentary press will let software shutdown
  while on - holding it for 4 second will force shut down
  when bat low during hibernate, shutdown
- Mod: changed to enable both mini and micro USB power bricks
- slikscreen TP18: VSYS_IN
- slikscreen TP19: VBUS
- USE FFC 21039-0732 @mouser
- Place close to SD card connector
- Silkscreen: USB OTG
- ECO K4R5,2: for VBUS detection
sheet 14
- ASPEN-DEBUG/SDIO/SSP/UART/MISC
- ECO: Uart connection fix
- Camera Power Down
- Check data in/out connection
- Short as possible
- HW ID numbers
  {MFP101:MFP100:MFP20}
  K4R3 ID = 010
  K4R5 ID = 011
- Notes:
  1. MFP110 is dedicated for SPI NOR FLASH BOOT purpose
  2. A_ISET: connect 6.04Kohm 1% resistor to ground
- ECO K4R5,5: HW revision strap change
- SYSTEM CLOCK
- Do NOT remove Q29, Q30 until pre-program part used
- increased C211 for possible
  reset too short issue
sheet 15
- K4R3.3 Circuit changes from K4R3.2
  - P10 remove R542,R548 Q162, Q173, replace with D39,D40
        revise otg_chgr33 to inverted Q177 mosfet,
  - P12 U185 part changed to NC7ST32P5X
        remove Q165/Q175
- K4R3.2 Circuit changes from K4R3.1
  - P7,P13: changed common mode chokes
  - P12: remove CM8 for high DC drop
  - P12: replace L36 with larger one
  - P13: change shield mounting to 16 clips
- K4R3.1 Circuit changes from K4R3
  - P10,P13: added USB power common mode chokes
  - P10,P13: populated common mode chokes on USB data
  - P14-P16: change i2c mosfets
  - P14,P15: rewire programmer connector
  - P10: added micro USB pull up for detection
  - P12: remove Q163 VIN detection feature due to slow transition to battery
- K4R3 Circuit changes from K4R2
  - P01: install Q155 depopulate R336 for hibernate
  - P01: added GPIO for PIC programming controls
       ICSPDAT1 GPIO17
       ICSPCLK1 GPIO21
       VPP1_CTRL GPIO3
       ICSPDAT2 GPIO13
       ICSPCLK2 GPIO8
       VPP2_CTRL GPIO2
  - P02: signal MFP94 renamed to MFP95
  - P03: new mosfets for power sequence
  - P06: new values for antenna matching
  - P07: CE156 power switch added
  - P10: revised power input
       allow charging from both mini and micro bricks
       added shutdown control to PIC for low battery cut off to prevent over drain of battery
  - P12: U146 MAX17058 Symbol error fix
       new charger up to 2A switching to spped up charging
       added cutout switch to boost supply to avoid leak
  - P17: PIC programmer VPP supply and signals
- K4R3 Functional changes from K4R2
  - enable hibernate
  - enable miniUSB charging
  - PIC programmer
  - new charger
  - USB device power
sheet 16
- Battery, Charger, Gas Gauge and Boost
- For use with Lithium Ion 18650 batteries
- Place close to J50
- Place close D28
- Tss = 1/4 Cshdn = ~1mS
- SHDN=L if VUSB_otg=5V
- SHDN=L if VUSB_SER present
- R586 vs charge current
  80K ->  1600
  70K ->  1400
  60K ->  1200 (default)
  50K ->  1000
  40K ->   800
  30K ->   600
  20K ->   400
- need some driver migration
- I2C linux address: 0x36
- UART CBUS0 - need programming from PC
  Low when connected to Host (disable charger)
  High when connected to Brick
sheet 17
- USE FFC 21039-0732 @mouser
- Place close to pin
  wide trace forV5P0FEXT
- ECO: programming fix
- ECO 4: 5V feed to PIC
- Use OC for INTR
- I2C linux address: 0x20
- Note: Need location from ID
- RB5 = Connector ID
- PIN SWAP OK
